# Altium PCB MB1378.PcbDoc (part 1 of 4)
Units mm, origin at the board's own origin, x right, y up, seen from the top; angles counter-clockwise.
Board outline 54.22 x 80.1 mm, 4 copper layers (Top Layer, L2-GND, L3, Bottom Layer), stack 0.771 mm thick; 206 components, 159 nets, 727 pads, 330 vias.
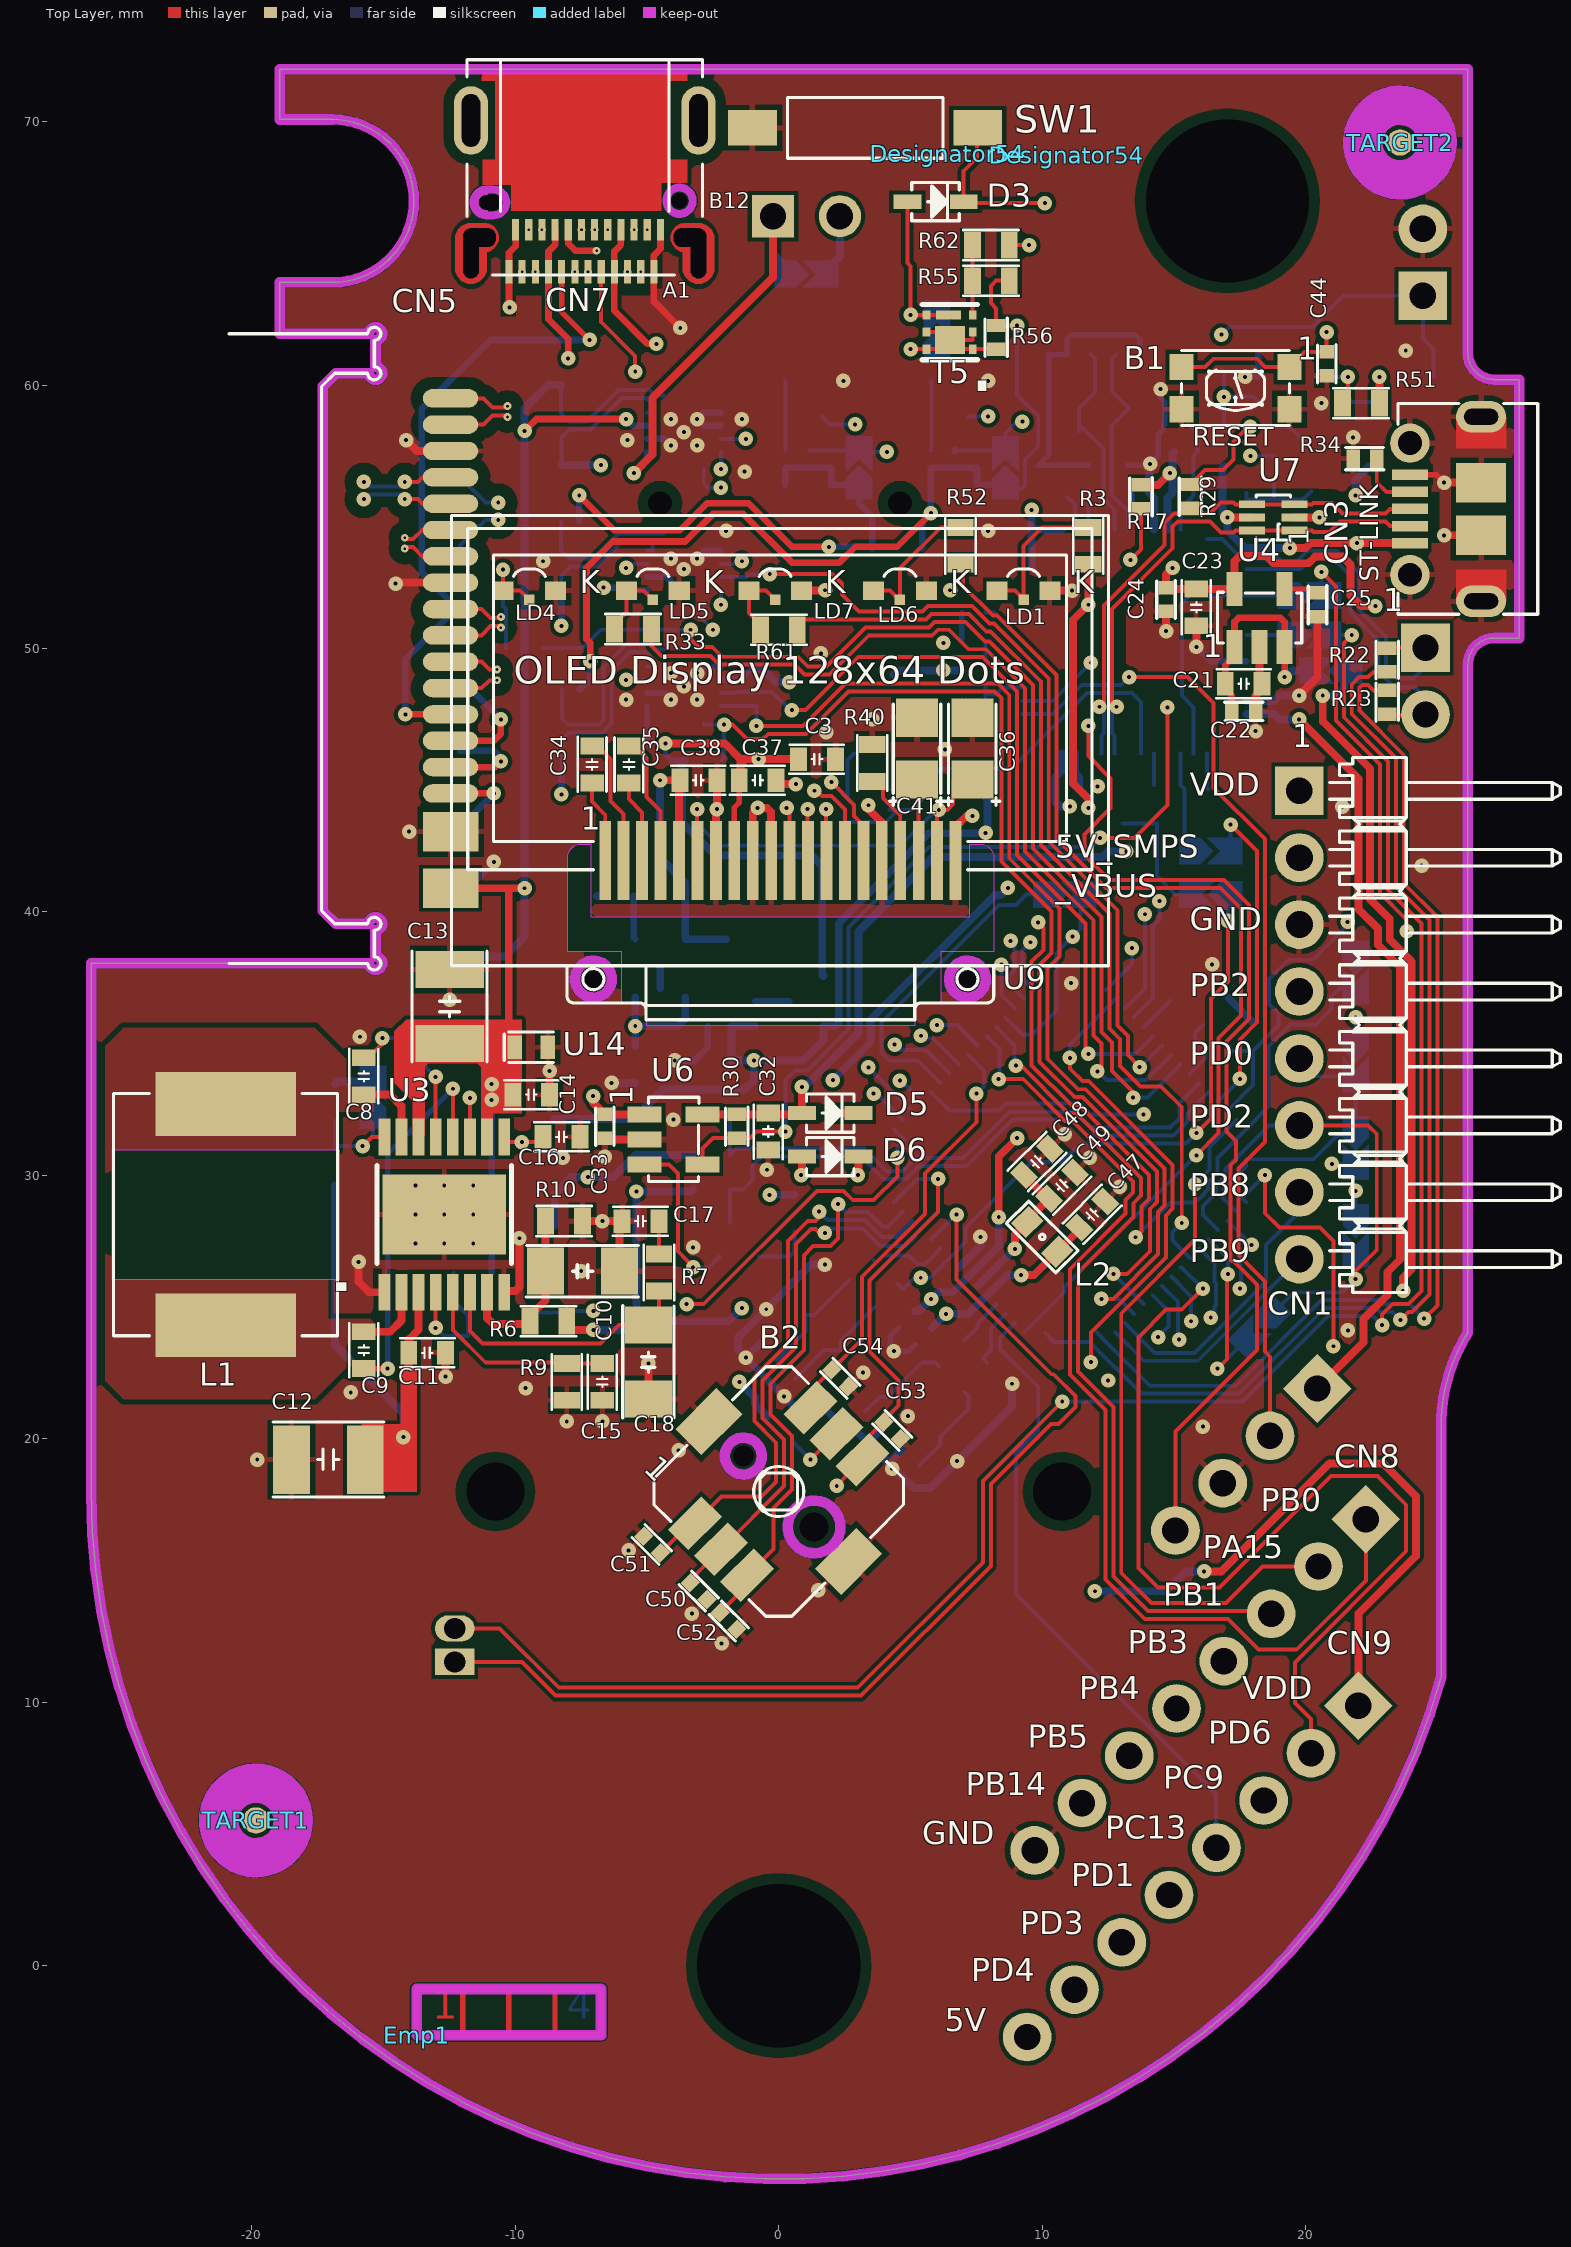
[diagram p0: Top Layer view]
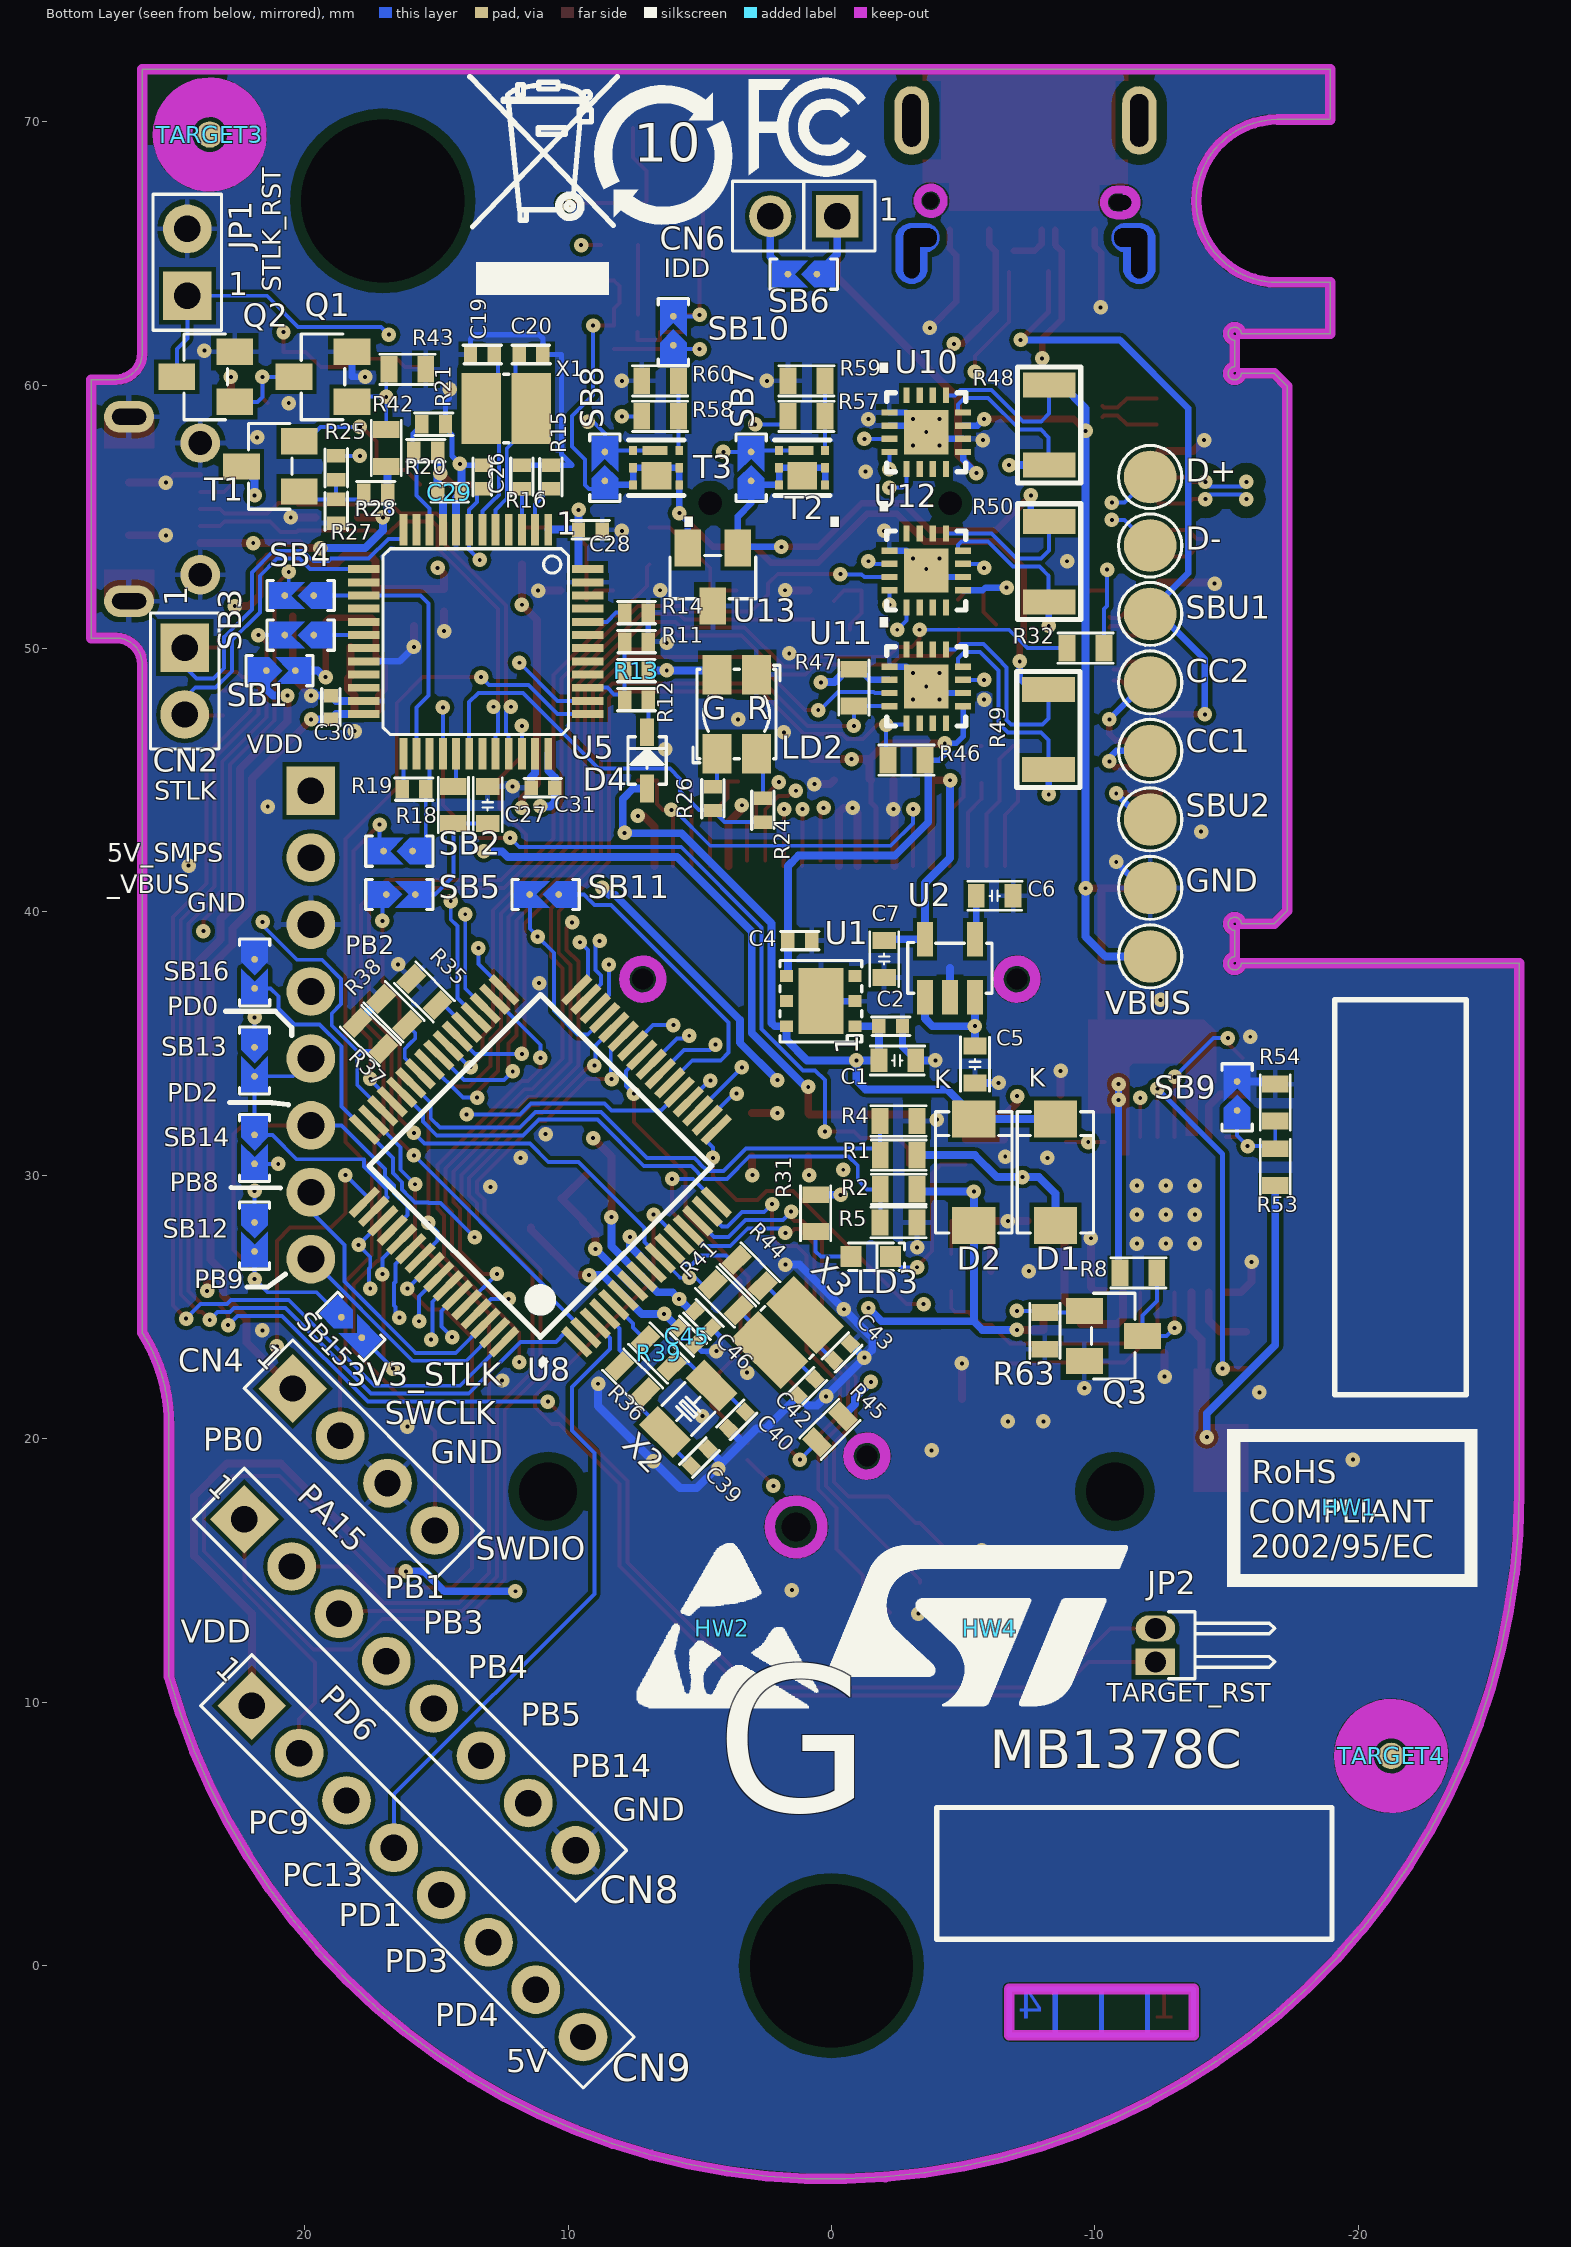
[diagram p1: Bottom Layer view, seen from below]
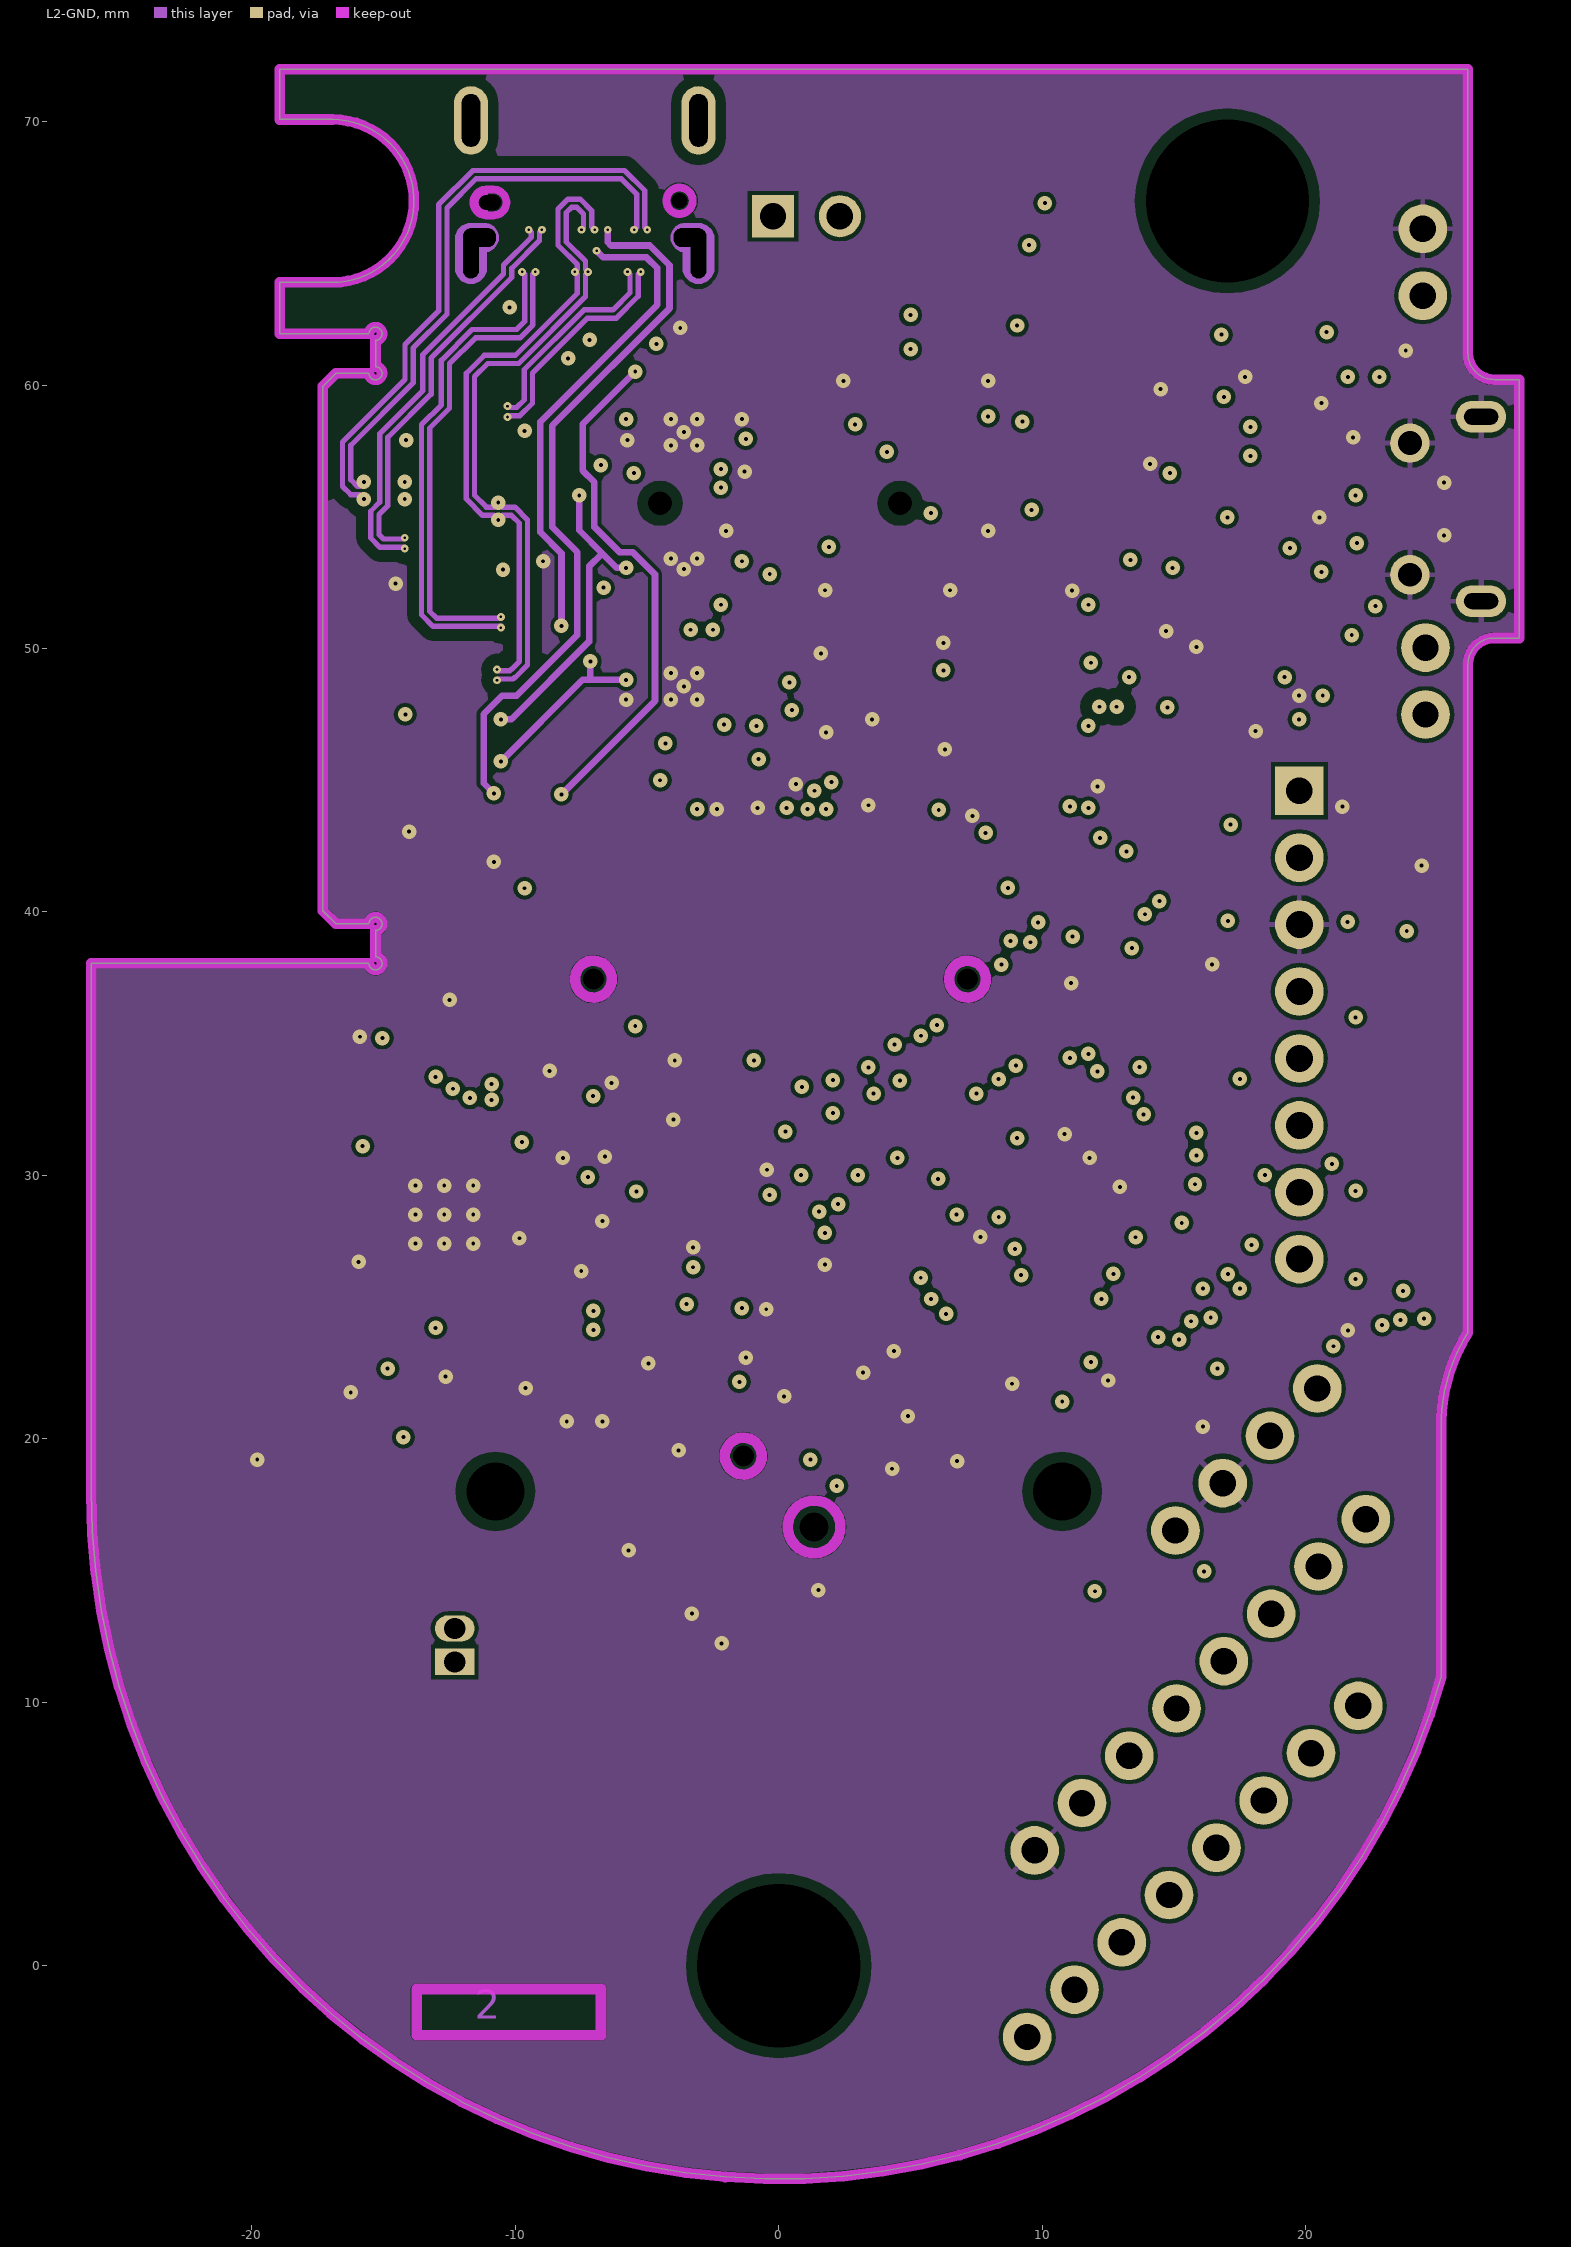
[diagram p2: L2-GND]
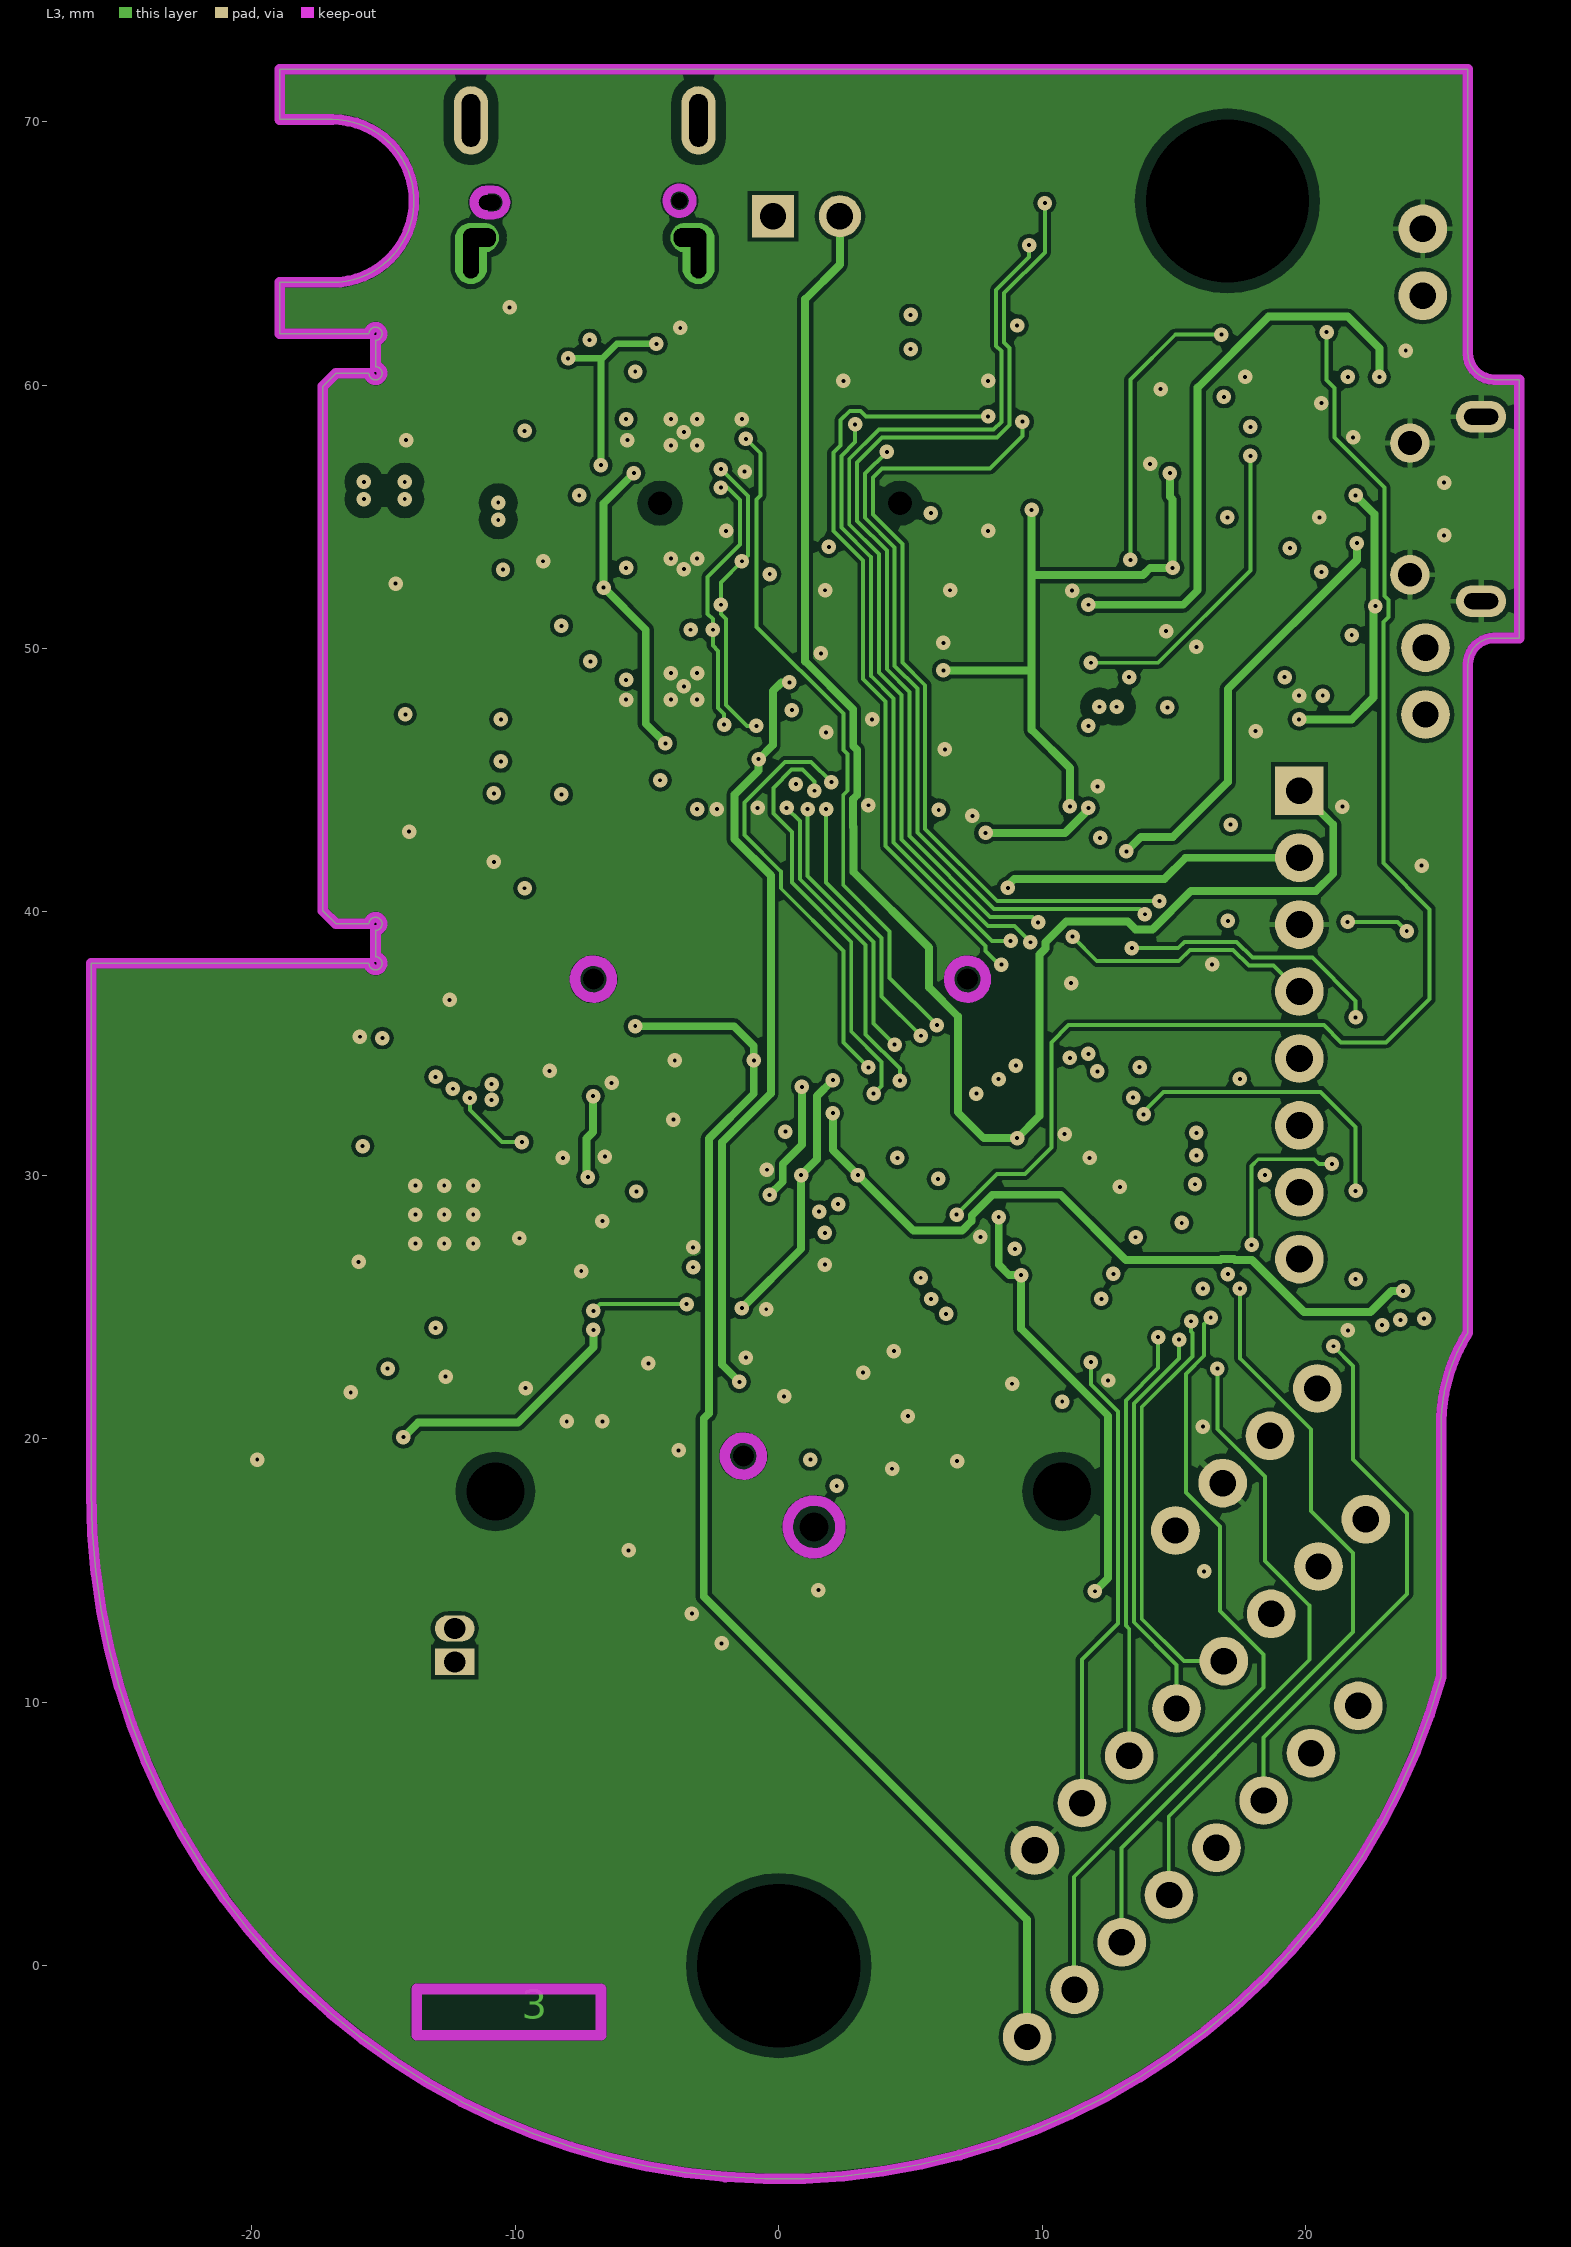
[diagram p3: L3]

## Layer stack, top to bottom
Top Solder: solder mask 0.015, Solder Resist, Dk 3.5
Top Layer: signal copper 0.035
Dielectric 1: core 0.1105, FR-4, Dk 3.95
L2-GND: signal copper 0.035
Dielectric 2: prepreg 0.41, Dk 3.95
L3: signal copper 0.035
Dielectric 3: core 0.1105, Dk 3.95
Bottom Layer: signal copper 0.035
Bottom Solder: solder mask 0.015, Solder Resist, Dk 3.5

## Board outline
-26.106,26.748 -26.106,27.448 -26.106,27.798 -26.106,35.499 -26.107,35.499 -26.107,38.049 -15.557,38.049 ccw(c-15.307,38.049) -15.307,38.299 -15.307,39.299 ccw(c-15.307,39.549) -15.557,39.549 -16.807,39.549 -17.307,40.049 -17.307,59.949 -16.807,60.449 -15.557,60.449 ccw(c-15.307,60.449) -15.307,60.699 -15.307,61.699 ccw(c-15.307,61.949) -15.557,61.949 -18.942,61.949 -18.942,63.896 -16.942,63.896 ccw(c-16.942,66.99) -16.942,70.083 -18.942,70.083 -18.942,71.999 4.624,71.999 14.545,71.999 26.163,71.999 26.163,62.147 26.163,61.209 ccw(c27.163,61.209) 27.163,60.209 28.109,60.209 28.109,50.399 27.163,50.399 ccw(c27.163,49.399) 26.163,49.399 26.163,46.114 26.163,25.294 26.163,24.023 26.124,23.96 26.086,23.897 26.048,23.834 26.011,23.771 25.975,23.707 25.939,23.642 25.905,23.578 25.871,23.513 25.837,23.447 25.805,23.381 25.773,23.315 25.742,23.249 25.712,23.182 25.682,23.115 25.654,23.047 25.626,22.979 25.599,22.911 25.572,22.843 25.547,22.774 25.522,22.705 25.498,22.636 25.474,22.566 25.452,22.497 25.43,22.427 25.409,22.356 25.389,22.286 25.37,22.215 25.351,22.144 25.333,22.073 25.316,22.002 25.3,21.93 25.285,21.858 25.27,21.786 25.257,21.714 25.244,21.642 25.232,21.57 25.22,21.497 25.21,21.424 25.2,21.351 25.191,21.278 25.183,21.205 25.176,21.132 25.17,21.058 25.164,20.985 25.16,20.911 25.156,20.838 25.153,20.764 25.151,20.69 25.15,20.616 25.149,20.542 25.149,10.965 24.705,9.528 24.181,8.127 23.58,6.764 22.9,5.435 22.143,4.142 21.309,2.892 20.405,1.691 19.439,0.552 18.412,-0.528 17.323,-1.549 16.171,-2.511 14.964,-3.407 13.709,-4.23 12.416,-4.976 11.085,-5.645 9.715,-6.238 8.305,-6.754 6.865,-7.19 5.407,-7.541 3.938,-7.807 2.459,-7.988 0.97,-8.087 -0.531,-8.099 -2.035,-8.024 -3.527,-7.864 -5,-7.62 -6.455,-7.294 -7.892,-6.884 -9.31,-6.39 -10.7,-5.813 -12.052,-5.16 -13.356,-4.435 -14.615,-3.637 -15.829,-2.766 -16.996,-1.822 -18.11,-0.81 -19.162,0.261 -20.144,1.385 -21.06,2.562 -21.909,3.792 -22.69,5.077 -23.396,6.404 -24.023,7.766 -24.568,9.156 -25.032,10.574 -25.415,12.02 -25.715,13.495 -25.932,14.988 -26.062,16.49 -26.106,17.998

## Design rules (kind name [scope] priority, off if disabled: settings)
BoardOutlineClearance [All] p1 off: gap=0.6 ignorepadtopadclearanceinfootprint=FALSE
Clearance Clearance_Keepout [IsKeepout] p1: gap=0.01 ignorepadtopadclearanceinfootprint=TRUE
Clearance Clearance_PadNTH [(ObjectKind = 'Pad') And (Layer = 'MultiLayer') And (Net = 'No Net')] p2: gap=0.4 ignorepadtopadclearanceinfootprint=FALSE
Clearance "Clearance_Polygon to Polygon" [InPolygon vs InPolygon] p3: gap=0.2 ignorepadtopadclearanceinfootprint=TRUE
Clearance "Clearance_90Ohms to Plane" [InPolygon vs InDifferentialPairClass('90 Ohms')] p4: gap=0.45 ignorepadtopadclearanceinfootprint=TRUE
Clearance Clearance_CN7 [(ObjectKind = 'Pad') And (Name = 'CN7-M2') vs (ObjectKind = 'Pad') And (Name = 'CN7-M3')] p5: gap=0 ignorepadtopadclearanceinfootprint=TRUE
Clearance Clearance_90Ohms [InDifferentialPairClass('90 Ohms') vs InDifferentialPairClass('90 Ohms')] p6: gap=0.11 ignorepadtopadclearanceinfootprint=TRUE
Clearance "Clearance_Via to Pad" [IsVia vs IsPad] p7: gap=0.15 ignorepadtopadclearanceinfootprint=TRUE
Clearance [All] p8: gap=0.15 ignorepadtopadclearanceinfootprint=TRUE
ComponentClearance [All] p1: gap=0.2 collisioncheckmode=3 verticalgap=0.2 showdistances=FALSE
DiffPairsRouting "DiffPairsRouting_90 Ohms" [InDifferentialPairClass('90 Ohms')] p1: maxlimit=0.152 minlimit=0.11 mostfreqgap=0.152 toplayer_mingap=0.152 toplayer_minwidth=0.152 toplayer_maxwidth=0.152 toplayer_prefwidth=0.152 midlayer1_maxgap=0.11 midlayer1_prefgap=0.11 midlayer1_minwidth=0.202 midlayer1_maxwidth=0.202 midlayer1_prefwidth=0.202 midlayer2_maxgap=0.11 midlayer2_prefgap=0.11 midlayer2_minwidth=0.202 midlayer2_maxwidth=0.202 midlayer2_prefwidth=0.202 bottomlayer_mingap=0.152 bottomlayer_minwidth=0.152 bottomlayer_maxwidth=0.152 bottomlayer_prefwidth=0.152 maxuncoupledlength=12.7
DiffPairsRouting DiffPairsRouting_Other [InDifferentialPairClass('Other')] p2: maxlimit=0.15 minlimit=0.15 mostfreqgap=0.15 toplayer_minwidth=0.15 toplayer_maxwidth=0.3 toplayer_prefwidth=0.25 midlayer1_minwidth=0.15 midlayer1_maxwidth=0.3 midlayer1_prefwidth=0.25 midlayer2_minwidth=0.15 midlayer2_maxwidth=0.3 midlayer2_prefwidth=0.25 bottomlayer_minwidth=0.15 bottomlayer_maxwidth=0.3 bottomlayer_prefwidth=0.25 maxuncoupledlength=12.7
Height Height_H0 [TouchesRoom('RoomDefinition_H0') and (InLayerClass('ExtLayer'))] p1: minheight=0 maxheight=0 prefheight=0
Height Height_H0_1 [TouchesRoom('RoomDefinition_H0_1') and (InLayerClass('ExtLayer')) and not HasFootprint('CO_JAE_DX07S024JJ2')] p2: minheight=0 maxheight=0 prefheight=0
Height Height_H0_2 [TouchesRoom('RoomDefinition_H0_2') and (InLayerClass('ExtLayer'))] p3: minheight=0 maxheight=0 prefheight=0
Height Height_H0_3 [TouchesRoom('RoomDefinition_H0_3') and (InLayerClass('ExtLayer'))] p4: minheight=0 maxheight=0 prefheight=0
Height Height_H0_4 [(TouchesRoom('RoomDefinition_H0_4') and (InLayerClass('ExtLayer')))   and not (HasFootprint('SW_COTO-TECHNOLOGYT05-XXXX-G1') or  HasFootprint('CO_JAE_DX07S024JJ2'))] p5: minheight=0 maxheight=0 prefheight=0
Height Height_H1.8 [TouchesRoom('RoomDefinition_H1.8')  and (OnLayer('Top Layer'))   and not HasFootprint('SWI_XIEJIA_MT-008A_6P')] p6: minheight=0 maxheight=1.8 prefheight=1.8
Height [All] p7: minheight=0 maxheight=25.4 prefheight=12.7
HoleSize [All] p1: absolutevalues=TRUE maxlimit=10 minlimit=0.025 maxpercent=80.000 minpercent=20.000
MinimumSolderMaskSliver [All] p1: minsoldermaskwidth=0.1
PlaneConnect [All] p1: planeconnectstyle=Relief reliefexpansion=0.508 reliefentries=4 reliefconductorwidth=0.21 reliefairgap=0.21
PolygonConnect PolygonConnect_DC [All vs InNet('NetC8_2')   OR InNet('NetC9_2')] p1: connectstyle=Direct reliefconductorwidth=0.254 reliefentries=4 polygonreliefangle="90 Angle" airgapwidth=0.254
PolygonConnect PolygonConnect_via [IsVia] p2: connectstyle=Direct reliefconductorwidth=0.254 reliefentries=4 polygonreliefangle="90 Angle" airgapwidth=0.254
PolygonConnect [All] p3: connectstyle=Relief reliefconductorwidth=0.2 reliefentries=4 polygonreliefangle="90 Angle" airgapwidth=0.2
RoomDefinition RoomDefinition_H1.8 [False] p1: confinementstyle=ConfineIn formatcopy=TRUE lockcomponents=FALSE outline -13.079,17.999 ccw(c-0.001,17.999) -0.001,4.921 ccw(c-0.001,17.999) 13.077,17.999 ccw(c-0.001,17.999) -0.001,31.077 ccw(c-0.001,17.999)
RoomDefinition RoomDefinition_H_1 [False] p2: confinementstyle=ConfineIn formatcopy=TRUE lockcomponents=FALSE outline -18.942,71.999 ccw(c-0.936,71.041) -18.942,70.083 ccw(c-17.942,107.718) -16.942,70.083 ccw(c0.029,246.574) -16.363,70.029 ccw(c37.887,251.196) -15.766,69.851 ccw(c80.478,247.308) -15.194,69.542 ccw(c115.761,239.422) -14.923,69.333 ccw(c122.954,212.641) -14.683,69.103 ccw(c130.45,179.982) -14.315,68.623 ccw(c132.439,141.399) -14.056,68.103 ccw(c175.812,119.278) -13.889,67.488 ccw(c160.862,78.987) -13.85,66.906 ccw(c185.088,39.67) -13.939,66.249 ccw(c167.153,-0.127) -14.167,65.624 ccw(c131.417,-24.78) -14.481,65.117 ccw(c106.065,-45.946) -14.866,64.697 ccw(c79.77,-61.196) -15.307,64.364 ccw(c54.188,-73.648) -15.796,64.117 ccw(c30.891,-97.145) -16.366,63.951 ccw(c-2.009,-91.564) -16.942,63.896 ccw(c-17.939,45.604) -18.943,63.896 ccw(c16.625,62.926) -18.942,61.949 ccw(c-17.125,134.458) -15.307,61.949 ccw(c-2.656,61.055) -15.327,61.604 ccw(c-17.016,67.007) -11.355,67.009 ccw(c-17.017,67.01) -14.339,71.999 -14.615,71.999
RoomDefinition RoomDefinition_H0_4 [False] p3: confinementstyle=ConfineOut formatcopy=TRUE lockcomponents=FALSE outline 12.146,68.019 14.675,68.019 14.675,71.959 -1.905,71.959 -1.905,68.019
RoomDefinition RoomDefinition_H0_3 [False] p4: confinementstyle=ConfineIn formatcopy=TRUE lockcomponents=FALSE outline 11.373,66.99 ccw(c17.036,66.99) 17.036,61.327 ccw(c17.036,66.99) 22.699,66.99 ccw(c17.036,66.99) 17.036,72.653 ccw(c17.036,66.99)
RoomDefinition RoomDefinition_H0_2 [False] p5: confinementstyle=ConfineIn formatcopy=TRUE lockcomponents=FALSE outline -5.663,0 ccw(c0,0) 0,-5.663 ccw(c0,0) 5.663,0 ccw(c0,0) 0,5.663 ccw(c0,0)
RoomDefinition RoomDefinition_H0_1 [False] p6: confinementstyle=ConfineIn formatcopy=TRUE lockcomponents=FALSE outline -14.284,17.999 ccw(c-10.756,17.999) -10.756,14.471 ccw(c-10.756,17.999) -7.228,17.999 ccw(c-10.756,17.999) -10.756,21.527 ccw(c-10.756,17.999)
RoomDefinition RoomDefinition_H0 [False] p7: confinementstyle=ConfineIn formatcopy=TRUE lockcomponents=FALSE outline 7.228,17.999 ccw(c10.756,17.999) 10.756,14.471 ccw(c10.756,17.999) 14.284,17.999 ccw(c10.756,17.999) 10.756,21.527 ccw(c10.756,17.999)
RoutingLayers "RoutingLayers_90 Ohms" [InDifferentialPairClass('All Differential Pairs')] p1: top layer_v5=TRUE mid layer 1_v5=TRUE mid layer 2_v5=FALSE bottom layer_v5=TRUE
RoutingLayers [All] p2: top layer_v5=TRUE mid layer 1_v5=TRUE mid layer 2_v5=TRUE bottom layer_v5=TRUE
RoutingVias RoutingVias_PWR [InNetClass('PWR')] p1: holewidth=0.15 width=0.55 viastyle="Through Hole" minholewidth=0.15 minwidth=0.55 maxholewidth=0.15 maxwidth=0.55
RoutingVias [All] p2: holewidth=0.15 width=0.55 viastyle="Through Hole" minholewidth=0.1 minwidth=0.3 maxholewidth=0.15 maxwidth=0.55
ShortCircuit ShortCircuit_CN7 [InPadClass('CN7') vs isvia] p1: allowed=TRUE
ShortCircuit ShortCircuit_PT [(ObjectKind = 'Pad') And (Name Like 'PA*-1')    or      (ObjectKind = 'Pad') And (Name Like 'PB*-1')    or (ObjectKind = 'Pad') And (Name Like 'PC*-1') or    (ObjectKind = 'Pad') And (Name Like 'PD*-1')        or (ObjectKind = 'Pad') And (Name = 'CC1-1')  or (ObjectKind = 'Pad') And (Name = 'SBU1-1')  or (ObjectKind = 'Pad') And (Name = 'GND-1') vs IsVia] p2: allowed=TRUE
ShortCircuit "ShortCircuit_Pad to vias" [(ObjectKind = 'Pad') And (Name = 'U10-17')   or  (ObjectKind = 'Pad') And (Name = 'U11-17')    or (ObjectKind = 'Pad') And (Name = 'U12-17')   or           (ObjectKind = 'Pad') And (Name = 'U6-9')          or  (ObjectKind = 'Pad') And (Name = 'U3-17') vs isvia and InNet('GND')] p3: allowed=TRUE
ShortCircuit [All] p4: allowed=FALSE
SilkToSilkClearance [All] p1: silktosilkclearance=0.2
SilkToSolderMaskClearance [IsPad] p1: minsilkscreentomaskgap=0.2 clearancetoexposedcopper=TRUE
SolderMaskExpansion SolderMaskExpansion_Vias [IsVia] p1: expansion=-2
SolderMaskExpansion [All] p2: expansion=0.102
Width Width_PWR [InNetClass('PWR')] p1: maxlimit=0.3 minlimit=0.15 preferedwidth=0.25
Width [All] p2: maxlimit=1 minlimit=0.15 preferedwidth=0.25
20 further rules are at their usual default settings.

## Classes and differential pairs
differential pair class Other: CC1 CC2 VBUS
pad class CN7: CN7-A1 CN7-A2 CN7-A3 CN7-A4 CN7-A5 CN7-A6 CN7-A7 CN7-A8 CN7-A9 CN7-A10 CN7-A11 CN7-A12 CN7-B1 CN7-B2 CN7-B3 CN7-B4 CN7-B5 CN7-B6 CN7-B7 CN7-B8 CN7-B9 CN7-B10 CN7-B11 CN7-B12
component class "USB Type C": CC1 CC2 CN5 CN7 D3 D+ D- GND R46 R47 R48 R49 R50 R55 R56 R57 R58 R59 R60 R62 SB7 SB8 SB10 SB16 SBU1 SBU2 SW1 T2 T3 T5 U10 U11 U12 U13 VBUS
component class U_Mechanical: HW1 HW2 HW4
component class U_Power_Supply: C1 C2 C3 C4 C5 C6 C7 C8 C9 C10 C11 C12 C13 C14 C15 C16 C17 C18 D1 D2 L1 LD1 Q3 R1 R2 R3 R4 R5 R6 R7 R8 R9 R10 R53 R54 R63 SB9 U1 U2 U3 U14
component class "STM32G0 MCU and display": B1 B2 C34 C35 C36 C37 C38 C39 C40 C41 C42 C43 C44 C45 C46 C47 C48 C49 C50 C51 C52 C53 C54 CN1 CN6 CN8 CN9 L2 LD4 LD5 LD6 LD7 R32 R33 R35 R36 R37 R38 R39 R40 R41 R44 R45 R52 R61 SB5 SB6 SB11 SB12 SB13 SB14 SB15 U8 U9 X2 X3
component class "ST-LINK v2.1": C19 C20 C21 C22 C23 C24 C25 C26 C27 C28 C29 C30 C31 C32 C33 CN2 CN3 CN4 D4 D5 D6 JP1 JP2 LD2 LD3 Q1 Q2 R11 R12 R13 R14 R15 R16 R17 R18 R19 R20 R21 R22 R23 R24 R25 R26 R27 R28 R29 R30 R31 R34 R42 R43 R51 SB1 SB2 SB3 SB4 T1 U4 U5 U6 U7 X1
differential pair class "90 Ohms": D1 RX1 RX2 TX1 TX2 USB_STLK
differential pair TX2: +TX2_P -TX2_N
differential pair TX1: +TX1_P -TX1_N
differential pair RX2: +RX2_P -RX2_N
differential pair RX1: +RX1_P -RX1_N
differential pair D1: +D1_P -D1_N
differential pair USB_STLK: +USB_STLK_P -USB_STLK_N
differential pair CC1: +CC1_P -CC1_N
differential pair CC2: +CC2_P -CC2_N
differential pair VBUS: +VBUS_P -VBUS_N

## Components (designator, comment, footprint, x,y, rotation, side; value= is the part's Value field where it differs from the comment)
B1 "SW-PUSH-CMS_KMR_NG" SWI_C&K_KMR721NG-LFS 17.338,59.887 r0 top value=KMR7
B2 "" SWI_XIEJIA_MT-008A_6P 0,17.999 r45 top locked value=MT-008A
C1 "" C0603 -2.497,34.362 r0 bottom value=1uF
C2 "" C0402 -2.247,35.662 r0 bottom value=100nF
C3 "" C0603 1.45,45.8 r0 top value=1uF
C4 "" C0402 1.203,38.912 r0 bottom value=100nF
C5 "" C0603 -5.447,34.212 r270 bottom value=1uF
C6 "" C0603 -6.197,40.612 r0 bottom value=10nF
C7 "" C0603 -1.997,38.212 r90 bottom value=2.2uF
C8 "​Footprint available C0603" C0603 -15.747,33.762 r270 top value=68nF
C9 "​Footprint available C0603" C0603 -15.747,23.362 r90 top value=68nF
C10 "​Footprint available" C1206_H1P25 -7.447,26.362 r180 top value=47pF
C11 "" C0603 -13.347,23.262 r180 top value=1uF
C12 "" C1210 -17.097,19.212 r0 top value=22uF
C13 "​Footprint available C1210" C1210 -12.497,36.412 r270 top value=10uF
C14 "Footprint available C0603" C0603 -9.397,33.062 r180 top value=1uF
C15 "​​Footprint available C0603" C0603 -6.697,22.162 r90 top value=33nF
C16 "" C0603 -8.247,31.462 r180 top value=4.7uF
C17 "​Footprint available C0603" C0603 -5.247,28.262 r0 top value=4.7nF
C18 "​Footprint available" C1206_H1P25 -4.947,22.912 r90 top value=47pF
C19 "" C0402 13.253,61.162 r0 bottom value=10pF
C20 "" C0402 11.403,61.162 r180 bottom value=10pF
C21 "" C0603 17.653,48.662 r0 top value=1uF
C22 "" C0402 17.653,47.612 r180 top value=100nF
C23 "" C0603 15.853,51.562 r90 top value=1uF
C24 "" C0402 14.703,51.862 r90 top value=100nF
C25 "" C0402 20.453,51.662 r90 top value=10nF
C26 "" C0402 13.253,56.512 r270 bottom value=100nF
C27 "Capacitor" C0603 13.053,44.062 r270 bottom value=20pF
C28 "" C0402 9.153,54.512 r0 bottom value=100nF
C29 "" C0402 14.503,55.912 r0 bottom value=100nF
C30 "" C0402 19.003,47.762 r270 bottom value=100nF
C31 "" C0402 10.953,44.712 r180 bottom value=100nF
C32 "" C0603 -0.397,31.662 r90 top value=1uF
C33 "" C0402 -6.597,31.862 r90 top value=100nF
C34 "" C0603 -7.087,45.599 r270 top value=1uF
C35 "" C0603 -5.687,45.599 r90 top value=1uF
C36 "​Footprint CPOL_TAJ-A_1206_H180" CPOL_TAJ-A_1206_H180 7.35,46.2 r90 top value=4.7uF
C37 "" C0603 -0.8,45 r0 top value=1uF
C38 "" C0603 -3.05,45 r0 top value=1uF
C39 "Capacitor" C0402 5.007,19.296 r135 bottom value=5.6pF
C40 "Capacitor" C0402 3.593,20.71 r315 bottom value=5.6pF
C41 "​Footprint CPOL_TAJ-A_1206_H180" CPOL_TAJ-A_1206_H180 5.25,46.2 r90 top value=4.7uF
C42 "" C0402 0.941,21.948 r315 bottom value=3.9pF
C43 "" C0402 -0.403,23.291 r135 bottom value=3.9pF
C44 "" C0402 20.803,60.812 r90 top value=100nF
C45 "" C0402 5.502,23.892 r45 bottom value=100nF
C46 "" C0402 4.865,24.529 r45 bottom value=100nF
C47 "Capacitor" C0603 11.903,28.512 r225 top value=4.7uF
C48 "Capacitor" C0603 9.803,30.512 r225 top value=1uF
C49 "" C0603 10.753,29.612 r225 top value=10nF
C50 "" C0402 -3.042,14.217 r135 top value=100nF
C51 "" C0402 -4.81,15.986 r315 top value=100nF
C52 "" C0402 -1.91,13.086 r135 top value=100nF
C53 "" C0402 4.3,20.319 r135 top value=100nF
C54 "" C0402 2.326,22.299 r135 top value=100nF
CC1 "Test Point" TP_SMD_2MM -12.097,46.112 r0 bottom
CC2 "Test Point" TP_SMD_2MM -12.097,48.712 r90 bottom
CN1 "Header 8x1" CO_SAMTEC_TSW-109-08-X-S-RA 19.763,35.709 r270 top locked value="USER CONNECTIVITY"
CN2 "" CON_SAMTEC_TSW-102-07-G-S 24.553,48.762 r270 bottom value="Header 2x1"
CN3 "" CON_USBMICROB_MOLEX_105017-0001_H2P90 28.113,55.299 r90 top locked value=USB_uB_105017-0001
CN4 "" CON_SAMTEC_TSW-104-07-G-S 17.753,19.212 r225 bottom value="Header 4x1"
CN5 "USB_TypeC_Plug_DX07P024MJ1" CO_ADVANCED-CONNECTEK_MB1378B-01 -12.457,49.999 r270 top locked value="USB Type-C Plug captive cable"
CN6 "" CON_988-JIUBABA_PHFS25-11-02-G0B115-T-1 1.053,66.412 r180 bottom
CN7 "​Footprint CO_JAE_DX07S024JJ2" CO_JAE_DX07S024JJ2 -7.365,64.999 r180 top locked value=DX07S024JJ2
CN8 "Header 8x1" CON_SAMTEC_TSW-108-07-X-S 16.001,10.66 r225 bottom value=USER1
CN9 "Header 8x1" CON_SAMTEC_TSW-108-07-X-S 15.716,3.576 r225 bottom value=USER2
D1 "STPS1L40M" DIO_SMA_1A_2K -8.503,30.117 r270 bottom value=STPS1L30A
D2 "STPS1L40M" DIO_SMA_1A_2K -5.403,30.117 r270 bottom value=STPS1L30A
D3 "" DIO_SOD323 5.953,66.962 r0 top value=BAT60JFILM
D4 "" DIO_SOD323 7,45.75 r90 bottom value=BAT60JFILM
D5 "" DIO_SOD323 1.953,32.362 r0 top value=BAT60JFILM
D6 "" DIO_SOD323 1.953,30.712 r0 top value=BAT60JFILM
D+ "Test Point" TP_SMD_2MM -12.097,56.512 r90 bottom
D- "Test Point" TP_SMD_2MM -12.097,53.912 r90 bottom
Designator54 "Comment" "LIFE_TIME - 5mm" 6.41,68.79 r0 top
Designator54 "Comment" TRASH 10.93,68.73 r0 top
Emp1 "" "Empilage 4C -Mid1+2 - SMALL" -13.747,-2.638 r0 top
GND "Test Point" TP_SMD_2MM -12.097,40.912 r90 bottom
HW1 "Logo" LOGO_ROHS -19.65,17.4 r180 bottom value="LOGO ROHS"
HW2 "Logo" LOGO_MAIN 4.15,12.8 r180 bottom value="LOGO ESD"
HW4 "Logo" LOGO_ST -6,12.8 r180 bottom value="LOGO ST"
JP1 "" CON_SAMTEC_TSW-102-07-G-S 24.453,64.662 r90 bottom value="ST-LINK RESET"
JP2 "Jumper_Header1.27 2x1 Fitted" CON_WP_707-2-02-2-20-00 -12.3,12.165 r90 bottom value="Shunt Fitted"
L1 "INDUCTOR_POWER" IND_WURTH_WE-LHMI-8040 -20.997,28.512 r270 top value="6.8µH 4.5A"
L2 "" L0603 10.003,27.662 r135 top
LD1 "LED_green" LED_BROADCOM-HSMG-C120 9.293,52.199 r0 top locked value="POWER 5V"
LD2 "" LED_BI-GR_HSMF-A201-A00J1 3.603,47.512 r0 bottom value=LD_BICOLOR_CMS
LD3 "LED_red" LED_0603_VISHAY_VLMS1300-GS08_RED_1A2K_H0P8 -1.497,26.912 r180 bottom value=RED
LD4 "LED_orange" LED_BROADCOM-HSML-C120 -9.467,52.199 r0 top locked value="TO REC"
LD5 "LED_orange" LED_BROADCOM-HSML-C120 -4.777,52.199 r0 top locked value="TO PLUG"
LD6 "LED_green" LED_BROADCOM-HSMG-C120 4.602,52.199 r0 top locked value=SINK/SPY
LD7 "LED_green" LED_BROADCOM-HSMG-C120 -0.137,52.199 r0 top locked value=SOURCE
"NOTE 1" "" "IMPEDANCE BOARD" -0.232,97.424 r0 top
Q1 "9013-SOT23" NPN_SOT23 19.303,60.312 r90 bottom value=BC817-25
Q2 "9013-SOT23" NPN_SOT23 23.753,60.312 r90 bottom value=BC817-25
Q3 "MOSFET_N-CHANNEL" ICC_SOT23-3L_H1P12 -10.7,23.9 r270 bottom value=NDS7002A
R1 "" R0603 -2.553,30.767 r180 bottom value=10K
R2 "" R0603 -2.553,29.467 r180 bottom value=10K
R3 "Resistor" R0603 11.75,53.9 r270 top value=470R
R4 "" R0603 -2.547,32.062 r0 bottom value=15K
R5 "" R0603 -2.547,28.212 r0 bottom value=15K
R6 "Resistor" R0603 -8.747,24.462 r0 top value=2M
R7 "" R0603 -4.547,26.312 r270 top value=15K
R8 "" R0603 -11.65,26.3 r0 bottom value=10K
R9 "" R0603 -8.047,22.162 r90 top value=43K
R10 "​Footprint R0603" R0603 -8.147,28.262 r180 top value=499K
R11 "" R0402 7.403,50.262 r0 bottom value=4K7
R12 "" R0402 7.403,48.062 r180 bottom value=2K7
R13 "" R0402 7.403,49.162 r180 bottom value=0R
R14 "" R0402 7.403,51.362 r0 bottom value=100K
R15 "" R0402 10.653,56.512 r90 bottom value=10K
R16 "" R0402 11.753,56.512 r270 bottom value=10K
R17 "" R0402 13.753,55.762 r90 top value=100K
R18 "Resistor" R0603 14.353,44.062 r270 bottom value=100R
R19 "" R0402 15.853,44.662 r0 bottom value=100R
R20 "" R0402 15.403,57.512 r0 bottom value=4K7
R21 "" R0402 15.103,58.512 r0 bottom value=4K7
R22 "" R0402 23.103,49.562 r270 top value=0R
R23 "" R0402 23.103,47.962 r270 top value=0R
R24 "" R0402 2.603,43.862 r270 bottom value=330R
R25 "" R0402 18.803,56.862 r90 bottom value=100R
R26 "" R0402 4.5,44.3 r270 bottom value=330R
R27 "" R0402 18.803,55.212 r90 bottom value=36K
R28 "" R0402 17.303,55.912 r0 bottom value=10K
R29 "" R0402 15.628,55.776 r90 top value=1K5
R30 "" R0402 -1.597,31.862 r90 top value=10K
R31 "Resistor" R0603 0.603,28.562 r270 bottom value=680R
R32 "Resistor" R0603 -9.647,50.012 r0 bottom value=470R
R33 "Resistor" R0603 -5.531,50.733 r0 top value=470R
R34 "" R0402 22.253,57.212 r0 top value=100K
R35 "" R0603 15.453,36.962 r225 bottom value=0R
R36 "" R0603 7.552,22.266 r225 bottom value=0R
R37 "" R0603 17.5,35.3 r225 bottom value=100K
R38 "" R0603 16.603,36.212 r225 bottom value=0R
R39 "" R0603 6.562,23.256 r225 bottom value=0R
R40 "" R0603 3.55,45.65 r270 top value=620K
R41 "" R0603 4.017,25.377 r225 bottom value=0R
R42 "Resistor" R0603 16.903,57.612 r90 bottom value=100K
R43 "Resistor" R0603 16.1,60.6 r0 bottom value=22K
R44 "" R0603 3.098,26.297 r225 bottom value=0R
R45 "" R0603 0.058,20.357 r315 bottom value=100R
R46 "Resistor" R0603 -2.847,45.762 r180 bottom value=1K
R47 "Resistor" R0603 -0.847,48.512 r90 bottom value=1K
R48 "​Footprint RESC3216X06N" RESC3216X06N -8.261,58.487 r90 bottom value="0.015R 1W 1%"
R49 "​Footprint RESC3216X06N" RESC3216X06N -8.237,46.924 r90 bottom value="0.015R 1W 1%"
R50 "​Footprint RESC3216X06N" RESC3216X06N -8.262,53.299 r90 bottom value="0.015R 1W 1%"
R51 "Resistor" R0603 22.103,59.312 r0 top value=100K
R52 "Resistor" R0603 6.9,53.9 r270 top value=470R
R53 "Resistor" R0603 -16.847,30.312 r270 bottom value=33K
R54 "Resistor" R0603 -16.847,32.762 r270 bottom value=22K
R55 "" R0603 8.053,63.962 r0 top value=1M
R56 "" R0402 8.253,61.812 r90 top value=5K1
R57 "Resistor" R0603 0.953,58.812 r0 bottom value=0R
R58 "Resistor" R0603 6.503,58.812 r0 bottom value=0R
R59 "" R0603 0.953,60.162 r180 bottom value=100K
R60 "" R0603 6.503,60.162 r180 bottom value=100K
R61 "Resistor" R0603 0.003,50.712 r0 top value=470R
R62 "Resistor" R0603 8.053,65.312 r180 top value=0R
R63 "Resistor" R0603 -8.1,24.1 r90 bottom value=47K
SB1 "" SOLDER-BRIDGE_R0603-0R 20.953,49.162 r180 bottom
SB2 "" SOLDER-BRIDGE_R0603-0R 16.403,42.312 r0 bottom
SB3 "" SOLDER-BRIDGE_R0603-0R 20.153,52.012 r0 bottom
SB4 "" SOLDER-BRIDGE_R0603-0R 20.153,50.512 r0 bottom locked
SB5 "" SOLDER-BRIDGE_R0603-0R 16.403,40.662 r180 bottom
SB6 "" SOLDER-BRIDGE_R0603-0R 1.053,64.212 r0 bottom
SB7 "SB_OFF" SOLDER-BRIDGE_R0603-0R 3.053,56.862 r90 bottom
SB8 "SB_OFF" SOLDER-BRIDGE_R0603-0R 8.603,56.862 r90 bottom
SB9 "" SOLDER-BRIDGE_R0603-0R -15.397,32.962 r90 bottom
SB10 "SB_OFF" SOLDER-BRIDGE_R0603-0R 6.003,62.012 r90 bottom
SB11 "SB_OFF" SOLDER-BRIDGE_R0603-0R 10.853,40.662 r0 bottom
SB12 "SB_OFF" SOLDER-BRIDGE_R0603-0R 21.903,27.712 r270 bottom
SB13 "SB_OFF" SOLDER-BRIDGE_R0603-0R 21.903,34.362 r270 bottom
SB14 "SB_OFF" SOLDER-BRIDGE_R0603-0R 21.903,31.037 r270 bottom
SB15 "SB_OFF" SOLDER-BRIDGE_R0603-0R 18.253,24.262 r225 bottom
SB16 "SB_OFF" SOLDER-BRIDGE_R0603-0R 21.9,37.7 r270 bottom
SBU1 "Test Point" TP_SMD_2MM -12.097,51.312 r90 bottom
SBU2 "Test Point" TP_SMD_2MM -12.097,43.512 r90 bottom
SW1 "SWITCH_CT05" SW_COTO-TECHNOLOGYT05-XXXX-G1 3.283,69.762 r0 top value="500mA Reed sensor"
T1 "" NPN_SOT23 21.303,56.912 r90 bottom value=9013-SOT23
T2 "​Footprint PowerFLAT_2x2" POWERFLAT_2X2 1.115,56.862 r0 bottom value=STL6N2VH5
T3 "​Footprint PowerFLAT_2x2" POWERFLAT_2X2 6.653,56.862 r0 bottom value=STL6N2VH5
T5 "​Footprint PowerFLAT_2x2" POWERFLAT_2X2 6.49,62.012 r180 top value=STL6N2VH5
TAB "Comment" "Design Information PCB Rigid - A4" 221.358,125.267 r0 top
TARGET1 "MIRE PCB" MIRE -19.847,5.512 r0 top
TARGET2 "MIRE PCB" MIRE 23.586,69.207 r0 top
TARGET3 "MIRE PCB" MIRE 23.603,69.512 r180 bottom
TARGET4 "MIRE PCB" MIRE -21.247,7.962 r180 bottom
U1 "" ICC_DFN6-EPAD_3X3_P095 0.403,36.612 r90 bottom value=LD39050PU33R
U2 "LP2985IM5-3.6/NOPB" REG_SOT23-5L -4.497,37.862 r180 bottom
U3 "​Footprint TSOP65P640X110_HS-17N" TSOP65P640X110_HS-17N -12.697,28.512 r90 top value=LTC3114-1
U4 "" REG_SOT23-5L 18.253,51.162 r0 top value=LD3985M33R
U5 "" ICC_LQFP48_7X7_P050 13.503,50.262 r0 bottom value=STM32F103CBT6
U6 "STMPS2141STR" MOS_SOT23-5L -3.997,31.362 r270 top
U7 "" ESD_SOT666 18.778,54.976 r90 top value=USBLC6-2P6
U8 "​Footprint TSQFP50P1200X1200X160-64N" TSQFP50P1200X1200X160-64N 11.053,30.362 r45 bottom value=STM32G071RBT6
U9 "OLED_RITDISPLAY_9OL9935701000" OLED_RITDISPLAY_9OL9935701000-MB1378B-01 -7.037,37.449 r0 top locked value=9OL9935701000
U10 "​Footprint QFN50P300X300X90-16N-S168" QFN50P300X300X90-16N-S168 -3.597,58.212 r180 bottom value=INA230
U11 "​Footprint QFN50P300X300X90-16N-S168" QFN50P300X300X90-16N-S168 -3.597,48.562 r180 bottom value=INA230
U12 "​Footprint QFN50P300X300X90-16N-S168" QFN50P300X300X90-16N-S168 -3.597,52.962 r180 bottom value=INA230
U13 "Footprint ESD_SOT23" ESD_SOT23 4.503,52.712 r0 bottom value=ESDA25L
U14 "ESD-TRANSIL" ESD_QFN1610_2N_1K_2A -9.397,34.862 r0 top value=ESDA25P35-1U1M
VBUS "Test Point" TP_SMD_2MM -12.097,38.312 r90 bottom
X1 "" CRY_NX3225GD_2P 12.353,59.112 r180 bottom value=NX3225GD-8.00M
X2 "" CRY_NX3215SA_2P 5.431,21.135 r135 bottom value=NX3215SA-32.768K
X3 "" CRY_NX3225GD_2P 1.683,24.034 r315 bottom value=NX3225GD-8.00M

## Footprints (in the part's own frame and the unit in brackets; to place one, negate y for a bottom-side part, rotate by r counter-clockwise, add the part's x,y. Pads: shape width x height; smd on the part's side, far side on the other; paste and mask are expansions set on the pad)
C0402 [mm]
  rect 0.51x0.56 smd mask+0.05: 1(-0.45,0) 2(0.45,0)
  silkscreen extent -0.72,-0.35 0.72,0.35, body extent -0.5,-0.3 0.5,0.3, height 0.4
C0603 [mm]
  rect 0.64x0.89 smd mask+0.05: 1(-0.7,0) 2(0.7,0)
  silkscreen extent -1.05,-0.55 1.02,0.55, body extent -0.9,-0.5 0.9,0.5, height 1.4
C1206_H1P25 [mm]
  rect 1.4x1.78 smd mask+0.05: 1(-1.4,0) 2(1.4,0)
  silkscreen extent -2.12,-0.97 2.15,0.97, body extent -1.7,-0.9 1.7,0.9, height 1.45
C1210 [mm]
  rect 1.4x2.6 smd mask+0.05: 1(-1.4,0) 2(1.4,0)
  silkscreen extent -2.1,-1.43 2.1,1.43, body extent -1.75,-1.35 1.75,1.35, height 2.5
CO_ADVANCED-CONNECTEK_MB1378B-01 [mm] "'Connector, USB TYpe-C Plug cable interface to PCB with specific layout"
  oval 0.7x2.1 smd: A1(-7.5,0) A2(-8.5,0) A3(-9.5,0) A5(4.5,0) A6(1.5,0) A7(0.5,0) A8(2.5,0) A10(-1.5,0) A11(-0.5,0) B1(-2.5,0) B2(-3.5,0) B3(-4.5,0) B5(3.5,0) B8(5.5,0) B10(-6.5,0) B11(-5.5,0)
  rect 1.5x2.1 smd: A4(9.1,0) A12(6.95,0)
  silkscreen extent -12.2,-8.4 12.2,-2.65, body extent -74.17,-17.23 11.7,0.43, height 8.39
CO_JAE_DX07S024JJ2 [mm] "USB Receptacle,Type-C, 24-Leads, Body 8.94x8.17mm, Pitch 0.50mm"
  rect 0.27x0.9 smd: A1(-2.625,0.7) A2(-2.125,0.7) A3(-1.625,0.7) A4(-1.125,0.7) A5(-0.625,0.7) A6(-0.125,0.7) A7(0.375,0.7) A8(0.875,0.7) A9(1.375,0.7) A10(1.875,0.7) A11(2.375,0.7) A12(2.875,0.7)
  rect 0.27x0.8 smd: B1(2.625,-0.9) B2(2.125,-0.9) B3(1.625,-0.9) B4(1.125,-0.9) B5(0.625,-0.9) B6(0.125,-0.9) B7(-0.375,-0.9) B8(-0.875,-0.9) B9(-1.375,-0.9) B10(-1.875,-0.9) B11(-2.375,-0.9) B12(-2.875,-0.9)
  round 0.5 hole 0.6 unplated: H1(-3.6,-2)
  oval 0.75x0.5 hole 0.6 slot 0.85 at 0 deg unplated: H2(3.6,-1.935)
  oval 1.3x2.6 hole 0.7 slot 2 at 90 deg: M1(-4.32,-5.05) M1(4.32,-5.05)
  round 0.4 hole 0.6 slot 1.9 at 90 deg mask+0: M2(-4.32,0) M2(4.32,0)
  round 0.4 hole 0.6 slot 1.2 at 0 deg mask+0: M3(-3.97,-0.65) M3(-3.97,-0.55) M3(3.97,-0.65) M3(3.97,-0.55)
  Top Layer region: -2.901,-2.692 -2.901,-1.625 2.794,-1.625 2.794,-2.6 3.875,-2.6 3.875,-3.55 3.4,-3.55 3.4,-6.547 3.9,-6.547 3.9,-6.85 -3.896,-6.85 -3.896,-6.55 -3.2,-6.55 -3.2,-3.55 -3.9,-3.55 -3.9,-2.692
  Keep-Out Layer circle w0.3: c-3.6,-2 r0.5
  Keep-Out Layer lines w0.1: 4.075,-1.925 cw(c3.725,-1.925) 3.725,-2.275 ; 4.075,-1.945 ccw(c3.725,-1.945) 3.725,-1.595
  Keep-Out Layer lines w0.3: 4.225,-1.925 cw(c3.725,-1.925) 3.725,-2.425 3.49,-2.425 ; 4.225,-1.945 ccw(c3.725,-1.945) 3.725,-1.445 3.49,-1.445 ; 3.71,-2.425 3.475,-2.425 cw(c3.475,-1.925) 2.975,-1.925 ; 3.475,-1.445 ccw(c3.475,-1.945) 2.975,-1.945
  Multi-Layer region: 4.439,-1.15 4.66,-1.059 4.829,-0.89 4.92,-0.669 4.92,0.669 4.829,0.89 4.66,1.059 4.439,1.15 4.201,1.15 3.98,1.059 3.811,0.89 3.72,0.669 3.72,-0.05 3.72,-0.05 3.625,-0.069 3.458,-0.169 3.335,-0.32 3.27,-0.503 3.27,-0.697 3.335,-0.88 3.458,-1.031 3.625,-1.131 3.72,-1.15 3.72,-1.15 3.72,-1.15
  Multi-Layer region: -4.439,-1.15 -4.66,-1.059 -4.829,-0.89 -4.92,-0.669 -4.92,0.669 -4.829,0.89 -4.66,1.059 -4.439,1.15 -4.201,1.15 -3.98,1.059 -3.811,0.89 -3.72,0.669 -3.72,-0.05 -3.72,-0.05 -3.625,-0.069 -3.458,-0.169 -3.335,-0.32 -3.27,-0.503 -3.27,-0.697 -3.335,-0.88 -3.458,-1.031 -3.625,-1.131 -3.72,-1.15 -3.72,-1.15
  silkscreen extent -4.47,-7.35 4.47,0.82, body extent -4.47,-7.35 4.47,0.82, height 3.17
CO_SAMTEC_TSW-109-08-X-S-RA [mm] "Header, .025 SQ Post Terminal Strip Assembly, 1x8 Pins, Right Angle, 2.54mm Pitch, Male"
  rect 1.85x1.85 hole 1: 1(-8.89,0)
  round 1.85 hole 1.02: 2(-6.35,0) 3(-3.81,0) 4(-1.27,0) 5(1.27,0) 6(3.81,0) 7(6.35,0) 8(8.89,0)
  silkscreen extent -10.16,1.15 10.16,9.9, body extent -10.16,-0.32 10.16,9.9, height 3.05
CON_988-JIUBABA_PHFS25-11-02-G0B115-T-1 [mm]
  rect 1.6x1.6 hole 1 mask+0.05: 1(1.27,0)
  round 1.6 hole 1 mask+0.05: 2(-1.27,0)
  silkscreen extent -2.71,-1.33 2.71,1.33, body extent -2.71,-1.33 2.71,1.33, height 8.85
CON_SAMTEC_TSW-102-07-G-S [mm]
  rect 1.85x1.85 / inner round 1.85 / far side rect 1.85x1.85 hole 1 mask+0.05: 1(-1.27,0)
  round 1.85 hole 1 mask+0.05: 2(1.27,0)
  silkscreen extent -2.58,-1.3 2.58,1.3, body extent -2.67,-1.3 2.58,1.3, height 8.38
CON_SAMTEC_TSW-104-07-G-S [mm]
  rect 1.85x1.85 / inner round 1.85 / far side rect 1.85x1.85 hole 1 mask+0.05: 1(-3.81,0)
  round 1.85 hole 1 mask+0.05: 2(-1.27,0) 3(1.27,0) 4(3.81,0)
  silkscreen extent -5.12,-1.3 5.12,1.3, body extent -5.21,-1.37 5.18,1.37, height 8.38
CON_SAMTEC_TSW-108-07-X-S [mm]
  rect 1.85x1.85 / inner round 1.85 / far side rect 1.85x1.85 hole 1 mask+0.05: 1(-8.89,0)
  round 1.85 hole 1 mask+0.05: 2(-6.35,0) 3(-3.81,0) 4(-1.27,0) 5(1.27,0) 6(3.81,0) 7(6.35,0) 8(8.89,0)
  silkscreen extent -10.27,-1.37 10.26,1.37, body extent -10.29,-1.37 10.26,1.37, height 8.38
CON_USBMICROB_MOLEX_105017-0001_H2P90 [mm]
  rect 0.4x1.35 smd mask+0.05: 1(-1.3,4.15) 2(-0.65,4.15) 3(0,4.15) 4(0.65,4.15) 5(1.3,4.15)
  round 1.5 hole 0.9 mask+0.05: 6(-2.5,4.15) 7(2.5,4.15)
  oval 1.2x1.9 hole 0.6 slot 1.3 at 90 deg mask+0.05: 8(3.5,1.45) 9(-3.5,1.45)
  rect 1.5x1.9 smd mask+0.05: 10(-1,1.45) 11(1,1.45)
  Top Layer region: 2.3,2.4 3.5,2.4 3.5,0.5 2.3,0.5
  Top Layer region: -3.5,2.4 -2.3,2.4 -2.3,0.5 -3.5,0.5
  silkscreen extent -4,-0.7 4,4.6, body extent -4.1,-1.15 4.1,4.66, height 2.9
CON_WP_707-2-02-2-20-00 [mm]
  rect 1x1.5 hole 0.8: 1(-0.635,0)
  oval 1x1.5 hole 0.8: 2(0.635,0)
  silkscreen extent -1.27,-4.53 1.27,-0.5, body extent -1.27,-4.53 1.27,0.22, height 2.1
CPOL_TAJ-A_1206_H180 [mm]
  rect 1.45x1.6 smd mask+0.05: 1(-1.175,0) 2(1.175,0)
  silkscreen extent -2.15,-1.05 1.7,1.05, body extent -1.7,-0.9 1.7,0.9, height 1.8
CRY_NX3215SA_2P [mm]
  rect 1x1.8 smd mask+0.05: 1(-1.25,0) 2(1.25,0)
  silkscreen extent -0.62,-0.8 0.63,0.8, body extent -1.65,-0.81 1.65,0.81, height 0.9
CRY_NX3225GD_2P [mm]
  rect 1.5x2.7 smd mask+0.05: 1(-0.95,0) 2(0.95,0)
  silkscreen extent -0.1,-1.3 0.1,1.3, body extent -1.65,-1.3 1.65,1.3, height 1
"Design Information PCB Rigid - A4" [mm] "Design Information PCB Rigid - Last Update : 2016-09-21"
DIO_SMA_1A_2K [mm]
  rect 1.4x1.64 smd mask+0.05: 1(2.015,0) 2(-2.015,0)
  silkscreen extent -2.3,-1.45 2.3,1.45, body extent -2.75,-1.45 2.75,1.45, height 2.7
DIO_SOD323 [mm]
  rect 1.06x0.54 smd mask+0.05: 1(-1.07,0) 2(1.07,0)
  silkscreen extent -0.9,-0.72 0.9,0.72, body extent -1.3,-0.78 1.3,0.78, height 1.17
"Empilage 4C -Mid1+2 - SMALL" [mm] "Empilage pour PCB 4 couches (Top+Bottom+MID1+MID2)"
  Top Layer lines w0.2: 1.75,0 1.75,1.75 ; 3.5,0 3.5,1.75 ; 5.25,0 5.25,1.75 ; 0,0 0,1.75 7,1.75 7,0 0,0
  Bottom Layer lines w0.2: 1.75,0 1.75,1.75 ; 3.5,0 3.5,1.75 ; 5.25,0 5.25,1.75 ; 0,0 7,0 7,1.75 0,1.75 0,0
  Keep-Out Layer lines w0.4: 0,0 0,1.75 7,1.75 7,0 0,0
ESD_QFN1610_2N_1K_2A [mm] "DFN, 2-Leads, Body 1.60x1.00mm"
  rect 0.55x0.9 smd mask+0.05: 1(-0.625,0) 2(0.625,0)
  silkscreen extent -1.02,-0.58 0.85,0.58, body extent -0.85,-0.55 0.85,0.55, height 0.6
ESD_SOT23 [mm]
  rect 1x1.4 smd mask+0.05: 1(-0.95,-1.1) 2(0.95,-1.1) 3(0,1.1)
  silkscreen extent -1.63,-0.82 1.63,0.82, body extent -1.56,-1.5 1.56,1.5, height 1.4
ESD_SOT666 [mm]
  rect 0.3x0.99 smd mask+0.05: 1(-0.5,-0.805) 2(0,-0.805) 3(0.5,-0.805) 4(0.5,0.805) 5(0,0.805) 6(-0.5,0.805)
  silkscreen extent -0.85,-0.65 0.85,0.65, body extent -0.85,-0.8 0.85,0.8, height 0.6
ICC_DFN6-EPAD_3X3_P095 [mm]
  rect 0.45x0.5 smd mask+0.05: 1(-0.95,-1.3) 2(0,-1.3) 3(0.95,-1.3) 4(0.95,1.3) 5(0,1.3) 6(-0.95,1.3)
  rect 2.5x1.7 smd mask+0.05: EP(0,0)
  silkscreen extent -1.55,-1.55 1.55,1.55, body extent -1.55,-1.55 1.55,1.55, height 1
ICC_LQFP48_7X7_P050 [mm]
  rect 0.3x1.2 smd mask+0.05: 1(-2.75,-4.25) 2(-2.25,-4.25) 3(-1.75,-4.25) 4(-1.25,-4.25) 5(-0.75,-4.25) 6(-0.25,-4.25) 7(0.25,-4.25) 8(0.75,-4.25) 9(1.25,-4.25) 10(1.75,-4.25) 11(2.25,-4.25) 12(2.75,-4.25) 25(2.75,4.25) 26(2.25,4.25) 27(1.75,4.25) 28(1.25,4.25) 29(0.75,4.25) 30(0.25,4.25) 31(-0.25,4.25) 32(-0.75,4.25) 33(-1.25,4.25) 34(-1.75,4.25) 35(-2.25,4.25) 36(-2.75,4.25)
  rect 1.2x0.3 smd mask+0.05: 13(4.25,-2.75) 14(4.25,-2.25) 15(4.25,-1.75) 16(4.25,-1.25) 17(4.25,-0.75) 18(4.25,-0.25) 19(4.25,0.25) 20(4.25,0.75) 21(4.25,1.25) 22(4.25,1.75) 23(4.25,2.25) 24(4.25,2.75) 37(-4.25,2.75) 38(-4.25,2.25) 39(-4.25,1.75) 40(-4.25,1.25) 41(-4.25,0.75) 42(-4.25,0.25) 43(-4.25,-0.25) 44(-4.25,-0.75) 45(-4.25,-1.25) 46(-4.25,-1.75) 47(-4.25,-2.25) 48(-4.25,-2.75)
  silkscreen extent -3.52,-3.52 3.52,3.52, body extent -4.5,-4.5 4.5,4.5, height 1.6
ICC_SOT23-3L_H1P12 [mm]
  rect 1x1.4 smd mask+0.05: 1(-0.95,-1.1) 2(0.95,-1.1) 3(0,1.1)
  silkscreen extent -1.63,-0.82 1.63,0.82, body extent -1.56,-1.25 1.56,1.25, height 1.12
"IMPEDANCE BOARD" [mm]
IND_WURTH_WE-LHMI-8040 [mm] "Power Choke, 2-Leads, Body 9.20.70x8.501x2mm (max), Pitch 3.7mm"
  rect 2.42x5.33 smd: 1(-4.2,0) 2(4.2,0)
  Top Layer keep-out region: -2.45,4.325 -2.45,-4.325 2.45,-4.325 2.45,4.325
  silkscreen extent -4.6,-4.25 4.6,4.25, body extent -4.72,-4.1 4.72,4.1, height 4.05
L0603 [mm]
  rect 0.8x0.95 smd mask+0.05: 1(-0.8,0) 2(0.8,0)
  silkscreen extent -1.33,-0.6 1.33,0.6, body extent -0.87,-0.47 0.87,0.47, height 0.95
LED_0603_VISHAY_VLMS1300-GS08_RED_1A2K_H0P8 [mm]
  rect 0.8x0.8 smd: 1(-0.75,0) 2(0.75,0)
  silkscreen extent -0.85,-0.53 1.28,0.53, body extent -0.85,-0.45 0.85,0.45, height 0.8
LED_BI-GR_HSMF-A201-A00J1 [mm]
  rect 1.1x1.5 smd mask+0.05: 1(-0.75,-1.5) 2(-0.75,1.5) 3(0.75,1.5) 4(0.75,-1.5)
  silkscreen extent -1.65,-1.85 1.65,1.85, body extent -1.5,-1.85 1.5,1.85, height 2.1
LED_BROADCOM-HSMG-C120 [mm] "LED, 2-Leads, Body 1.60x1.00x0.60, Green (BROADCOM-AVAGO)"
  rect 0.8x0.7 smd: 1(-1,0) 2(1,0)
  rect 0.4x0.4 smd: 1(0,-0.35)
  silkscreen extent -0.6,0.54 0.6,0.82, body extent -0.85,-0.28 0.85,0.83, height 0.7
LED_BROADCOM-HSML-C120 [mm] "LED, 2-Leads, Body 1.60x1.00x0.60, Orange (BROADCOM-AVAGO)"
  rect 0.8x0.7 smd: 1(-1,0) 2(1,0)
  rect 0.4x0.4 smd: 1(0,-0.35)
  silkscreen extent -0.6,0.54 0.6,0.82, body extent -0.85,-0.28 0.85,0.83, height 0.7
"LIFE_TIME - 5mm" [mm]
LOGO_MAIN [mm]
  silkscreen extent -3.24,-3.02 3.65,3.22
LOGO_ROHS [mm]
  silkscreen extent -4.63,-3.03 4.87,2.98
LOGO_ST [mm]
  silkscreen extent -6.18,-2.95 5.25,3.14
MIRE [mm] "Fiducial Target Round , Pad 1.0mm, Keepout 4.4mm"
  round 1 smd mask+1.5: 1(0,0)
  Top Layer keep-out circle w1.5: c0,0 r1.414
  body extent -0.5,-0.5 0.5,0.5, height 0.04
MOS_SOT23-5L [mm]
  rect 0.6x1.3 smd mask+0.05: 1(-0.95,-1.1) 2(0,-1.1) 3(0.95,-1.1) 4(0.95,1.1) 5(-0.95,1.1)
  silkscreen extent -1.6,-0.95 1.6,0.97, body extent -1.52,-1.25 1.52,1.25, height 1.45
NPN_SOT23 [mm]
  rect 1x1.4 smd mask+0.05: 1(-0.95,-1.1) 2(0.95,-1.1) 3(0,1.1)
  silkscreen extent -1.63,-0.82 1.63,0.82, body extent -1.56,-1.25 1.56,1.25, height 1.1
OLED_RITDISPLAY_9OL9935701000-MB1378B-01 [mm] "OLED, 20-Leads, Body 24.94x7.50x22.80mm, Pitch 0.30mm - MB1378B-01"
  rect 0.45x3 smd mask+0.051: 1(0.45,4.5) 2(1.15,4.5) 3(1.85,4.5) 4(2.55,4.5) 5(3.25,4.5) 6(3.95,4.5) 7(4.65,4.5) 8(5.35,4.5) 9(6.05,4.5) 10(6.75,4.5) 11(7.45,4.5) 12(8.15,4.5) 13(8.85,4.5) 14(9.55,4.5) 15(10.25,4.5) 16(10.95,4.5) 17(11.65,4.5) 18(12.35,4.5) 19(13.05,4.5) 20(13.75,4.5)
  round 0.5 hole 0.8 unplated mask+0.25: H1(0,0) H1(14.2,0)
  Top Layer keep-out region: -0.984,1.05 1.05,1.05 1.05,-0.903 2.016,-0.903 2.016,-1.75 12.216,-1.75 12.216,-0.903 13.2,-0.903 13.2,1.05 15.216,1.05 15.216,4.597 15.216,4.697 15.14,4.88 14.999,5.021 14.815,5.097 14.716,5.097 14.275,5.097 14.275,2.35 -0.075,2.35 -0.075,5.097 -0.483,5.097 -0.582,5.098 -0.767,5.022 -0.908,4.881 -0.984,4.697 -0.984,4.597
  Keep-Out Layer circle w0.4: c14.2,0 r0.7
  Keep-Out Layer circle w0.4: c0,0 r0.7
  silkscreen extent -5.39,-1.54 19.56,17.61, body extent -5.39,-1.54 26.1,24.35, height 4.2
POWERFLAT_2X2 [mm] "PowerFLAT, 6-Leads, Body 2.1x2.1mm"
  rect 0.3x0.35 smd: 1(-0.875,0.65) 2(-0.875,0) 3(-0.875,-0.65) 4(0.875,-0.65) 5(0.875,0) 6(0.875,0.65)
  rect 0.95x0.35 smd: 7(0.05,-0.65)
  rect 1.125x1.05 smd: 8(-0.012,0.3)
  silkscreen extent -1.05,-1.05 1.05,1.05, body extent -1,-1 1,1, height 0.75
QFN50P300X300X90-16N-S168 [mm] "QFN, 16-Leads, Body 3.15x31.5x1mm (max),Thermal Pad 1.8x1.8mm, Pitch 0.50mm"
  rect 0.7x0.7 on Bottom Paste: 0(-0.45,-0.45) 0(-0.45,0.45) 0(0.45,-0.45) 0(0.45,0.45)
  rect 0.6x0.24 smd: 1(-1.4,0.75) 2(-1.4,0.25) 3(-1.4,-0.25) 4(-1.4,-0.75) 9(1.4,-0.75) 10(1.4,-0.25) 11(1.4,0.25) 12(1.4,0.75)
  rect 0.24x0.6 smd: 5(-0.75,-1.4) 6(-0.25,-1.4) 7(0.25,-1.4) 8(0.75,-1.4) 13(0.75,1.4) 14(0.25,1.4) 15(-0.25,1.4) 16(-0.75,1.4)
  rect 1.68x1.68 smd paste-10: 17(0,0)
  silkscreen extent -1.5,-1.5 1.5,1.5, body extent -1.57,-1.57 1.58,1.58, height 1
R0402 [mm]
  rect 0.51x0.7 smd mask+0.05: 1(-0.45,0) 2(0.45,0)
  silkscreen extent -0.72,-0.43 0.72,0.43, body extent -0.52,-0.3 0.52,0.3, height 0.4
R0603 [mm]
  rect 0.64x1 smd mask+0.05: 1(-0.7,0) 2(0.7,0)
  silkscreen extent -1.05,-0.58 1.05,0.58, body extent -0.9,-0.5 0.9,0.5, height 0.56
REG_SOT23-5L [mm]
  rect 0.6x1.3 smd mask+0.05: 1(-0.95,-1.1) 2(0,-1.1) 3(0.95,-1.1) 4(0.95,1.1) 5(-0.95,1.1)
  silkscreen extent -1.6,-0.95 1.6,0.97, body extent -1.52,-1.25 1.52,1.25, height 1.1
RESC3216X06N [mm] "Chip Resistor, 2-Leads, Body 3.20x1.60mm"
  rect 0.95x2 smd: 1(-1.525,0) 2(1.525,0)
  silkscreen extent -2.2,-1.2 2.2,1.2, body extent -1.6,-0.8 1.6,0.8, height 0.55
SOLDER-BRIDGE_R0603-0R [mil]
  round 10 smd paste-393.7: 1(-19.68,0) 2(23.62,0)
  Top Layer region: -5.91,19.69 13.78,0 -5.91,-19.68 47.24,-19.68 47.24,19.69 -5.91,19.69
  Top Layer region: -47.24,-19.68 -47.24,19.69 -15.75,19.69 3.94,0 -15.75,-19.68 -47.24,-19.68
  silkscreen extent -50,-23 50,23, body extent -36,-20 36,20, height 22
SW_COTO-TECHNOLOGYT05-XXXX-G1 [mm] "Reed Switch, 2-Leads, Body 6.40x2.31x2.39mm"
  rect 1.85x1.35 smd: 1(-4.275,0) 2(4.275,0)
  silkscreen extent -2.95,-1.15 2.95,1.15, body extent -4.77,-1.15 4.77,1.15, height 2.39
SWI_C&K_KMR721NG-LFS [mm] "MCD-01510"
  rect 0.9x1 smd mask+0.05: 1(2.05,0.8) 2(2.05,-0.8) 3(-2.05,0.8) 4(-2.05,-0.8)
  silkscreen extent -2.05,-1.43 2.05,1.43, body extent -2.3,-1.5 2.3,1.5, height 2.5
SWI_XIEJIA_MT-008A_6P [mm]
  rect 1.8x1.1 smd mask+0.05: 1(-3.1,1.4) 2(-3.1,0) 3(-3.1,-1.4) 4(3.1,1.4) 5(3.1,0) 6(3.1,-1.4)
  rect 2.2x1.4 smd mask+0.05: 7(0,3.75) 8(0,-3.75)
  round 0.5 hole 0.8 unplated paste-10 mask+0.05: NPTH1(0,1.9)
  round 0.8 hole 1.1 unplated paste-10 mask+0.05: NPTH2(0,-1.9)
  Keep-Out Layer circle w0.4: c0,-1.9 r1
  Keep-Out Layer circle w0.4: c0,1.9 r0.7
  silkscreen extent -3.7,-3.7 3.7,3.7, body extent -3.85,-3.75 3.85,3.75, height 5
TP_SMD_2MM [mm]
  round 2 smd paste-10 mask+0.05: 1(0,0)
  silkscreen extent -1.2,-1.2 1.2,1.2
TRASH [mm]
TSOP65P640X110_HS-17N [mm] "TSOP, 16-Leads, Body 5.00x4.40mm, Pitch 0.65mm, Thermal Pad 3.58x2.94mm"
  rect 1.4x0.45 smd: 1(-2.95,2.275) 2(-2.95,1.625) 3(-2.95,0.975) 4(-2.95,0.325) 5(-2.95,-0.325) 6(-2.95,-0.975) 7(-2.95,-1.625) 8(-2.95,-2.275) 9(2.95,-2.275) 10(2.95,-1.625) 11(2.95,-0.975) 12(2.95,-0.325) 13(2.95,0.325) 14(2.95,0.975) 15(2.95,1.625) 16(2.95,2.275)
  rect 3.05x4.7 smd paste+0: 17(0,0)
  silkscreen extent -1.85,-2.55 1.85,2.55, body extent -3.2,-2.55 3.2,2.55, height 1.1
TSQFP50P1200X1200X160-64N [mm] "TSQFP, 64-Leads, Body 10.00x10.00mm, Pitch 0.50mm"
  rect 1.4x0.3 smd: 1(-5.7,3.75) 2(-5.7,3.25) 3(-5.7,2.75) 4(-5.7,2.25) 5(-5.7,1.75) 6(-5.7,1.25) 7(-5.7,0.75) 8(-5.7,0.25) 9(-5.7,-0.25) 10(-5.7,-0.75) 11(-5.7,-1.25) 12(-5.7,-1.75) 13(-5.7,-2.25) 14(-5.7,-2.75) 15(-5.7,-3.25) 16(-5.7,-3.75) 33(5.7,-3.75) 34(5.7,-3.25) 35(5.7,-2.75) 36(5.7,-2.25) 37(5.7,-1.75) 38(5.7,-1.25) 39(5.7,-0.75) 40(5.7,-0.25) 41(5.7,0.25) 42(5.7,0.75) 43(5.7,1.25) 44(5.7,1.75) 45(5.7,2.25) 46(5.7,2.75) 47(5.7,3.25) 48(5.7,3.75)
  rect 0.3x1.4 smd: 17(-3.75,-5.7) 18(-3.25,-5.7) 19(-2.75,-5.7) 20(-2.25,-5.7) 21(-1.75,-5.7) 22(-1.25,-5.7) 23(-0.75,-5.7) 24(-0.25,-5.7) 25(0.25,-5.7) 26(0.75,-5.7) 27(1.25,-5.7) 28(1.75,-5.7) 29(2.25,-5.7) 30(2.75,-5.7) 31(3.25,-5.7) 32(3.75,-5.7) 49(3.75,5.7) 50(3.25,5.7) 51(2.75,5.7) 52(2.25,5.7) 53(1.75,5.7) 54(1.25,5.7) 55(0.75,5.7) 56(0.25,5.7) 57(-0.25,5.7) 58(-0.75,5.7) 59(-1.25,5.7) 60(-1.75,5.7) 61(-2.25,5.7) 62(-2.75,5.7) 63(-3.25,5.7) 64(-3.75,5.7)
  silkscreen extent -4.6,-4.6 4.6,4.6, body extent -6,-6 6,6, height 1.6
